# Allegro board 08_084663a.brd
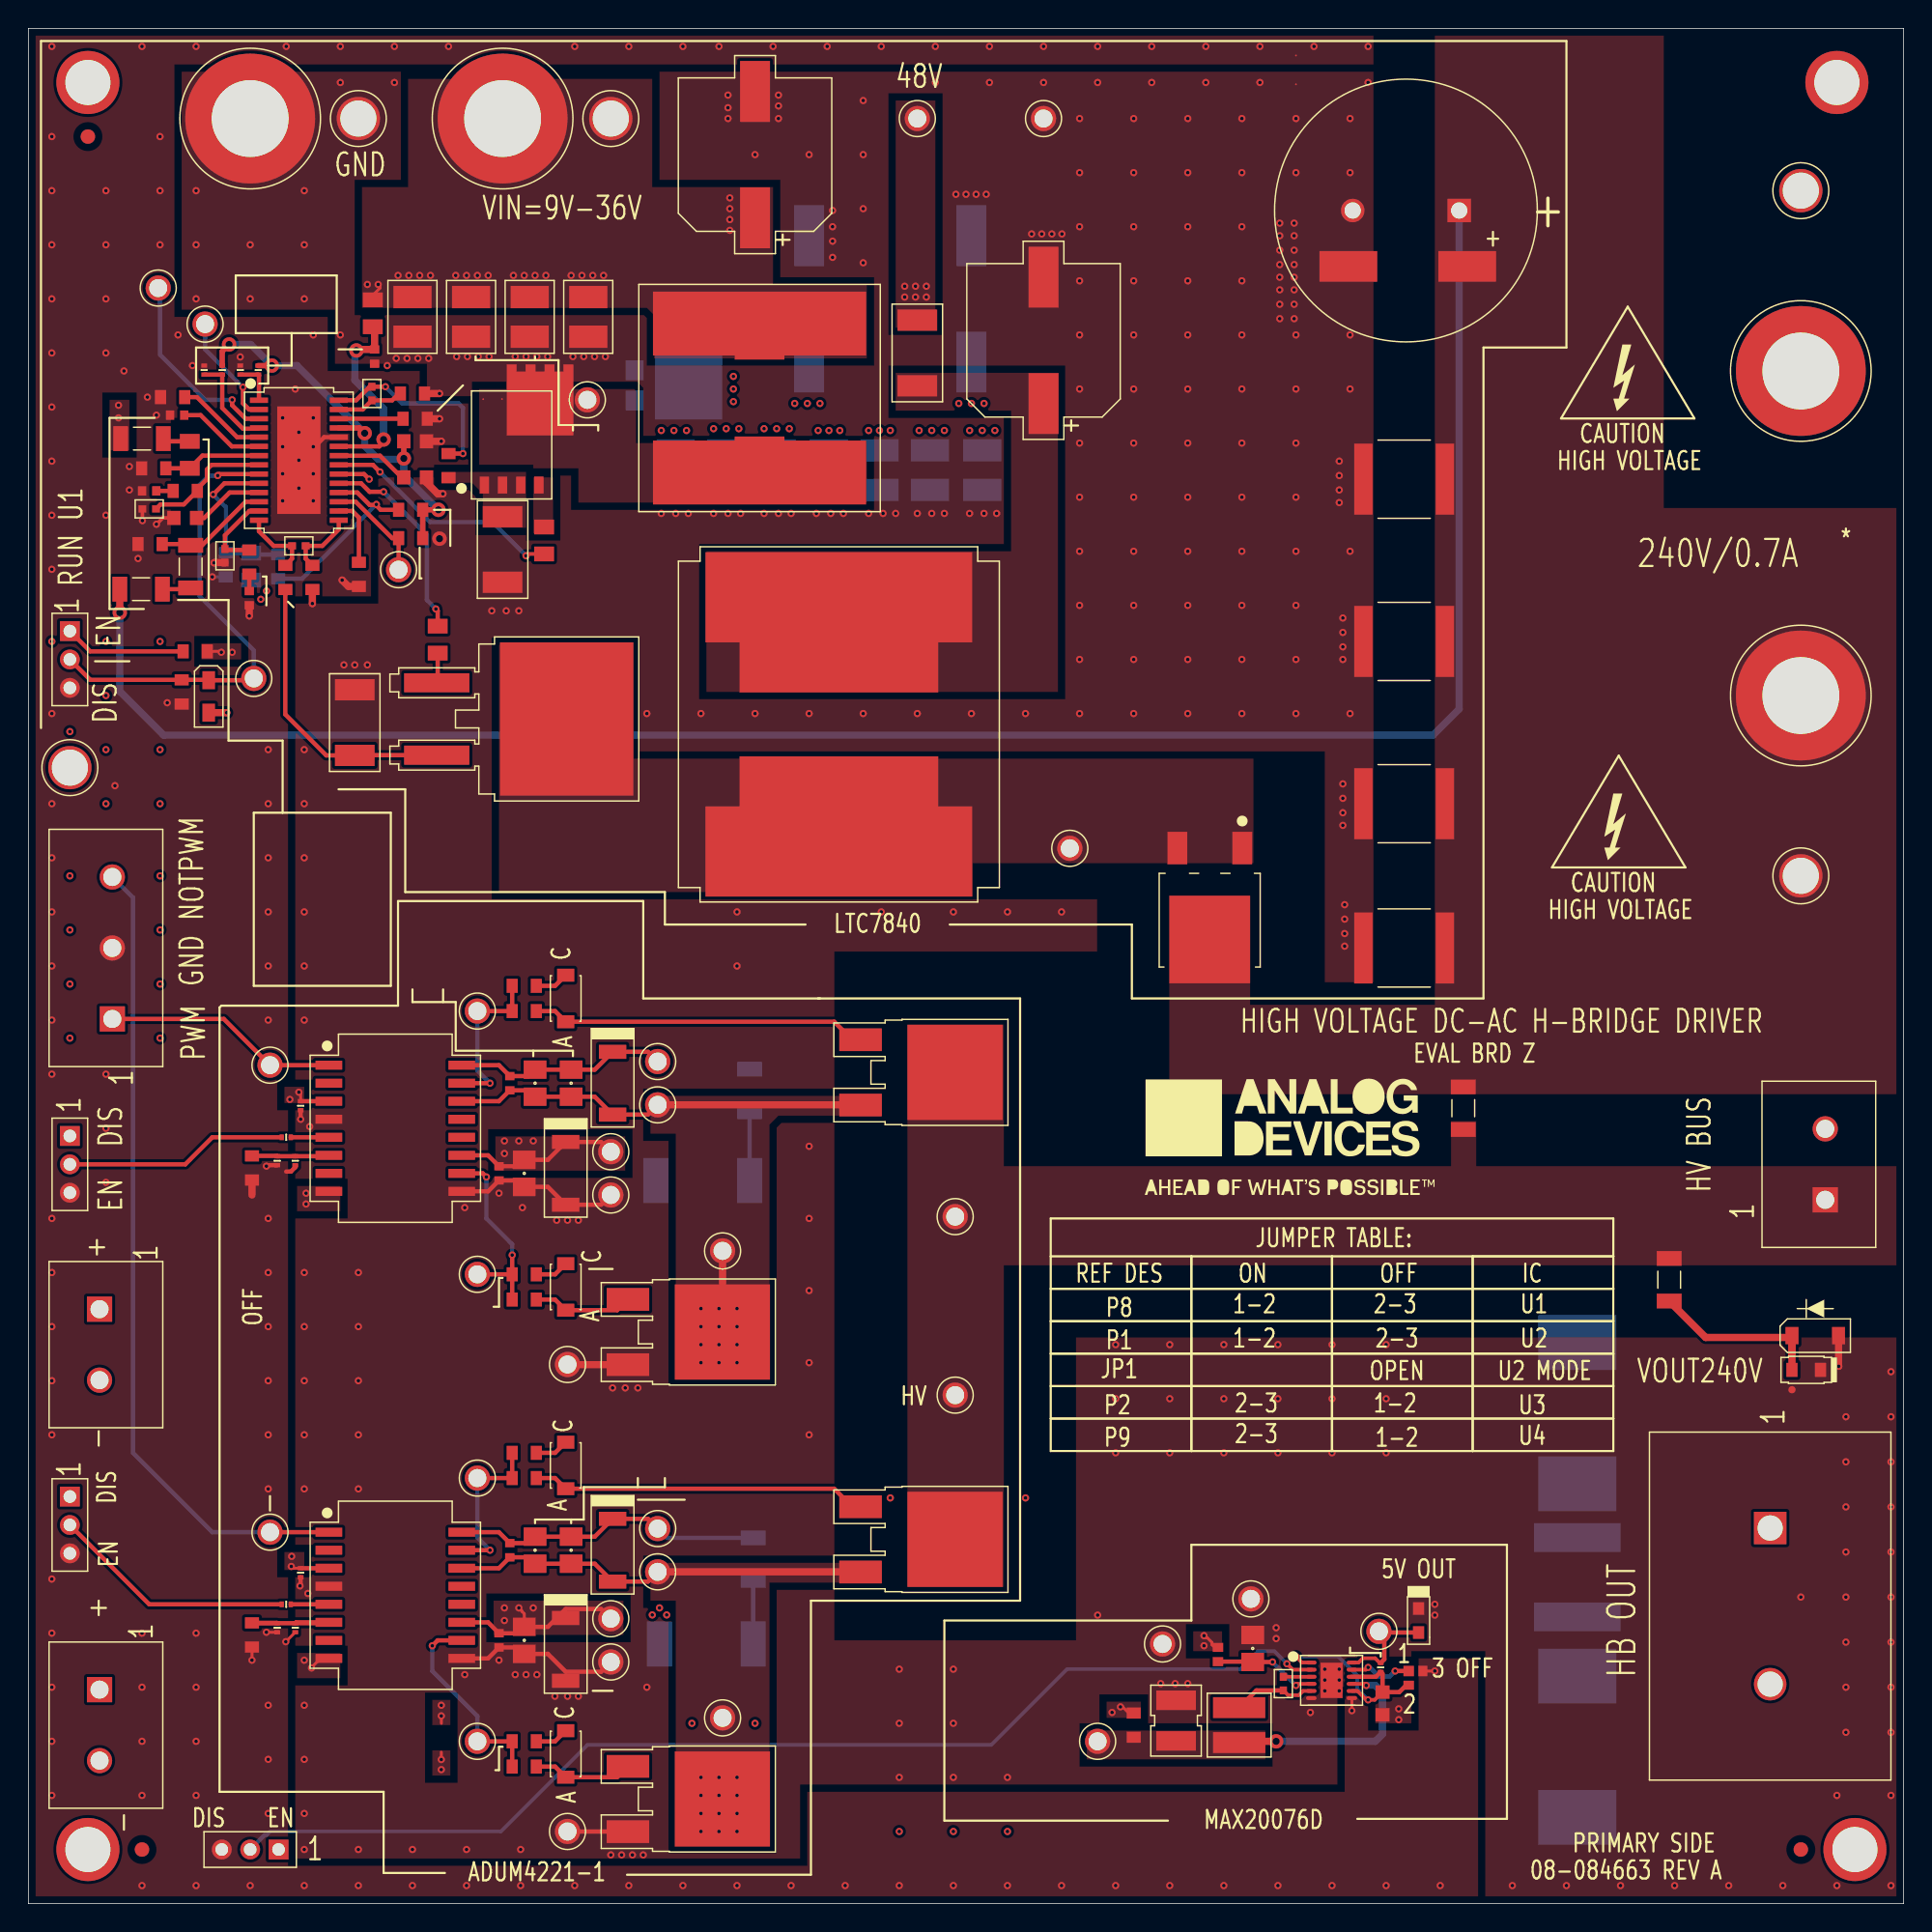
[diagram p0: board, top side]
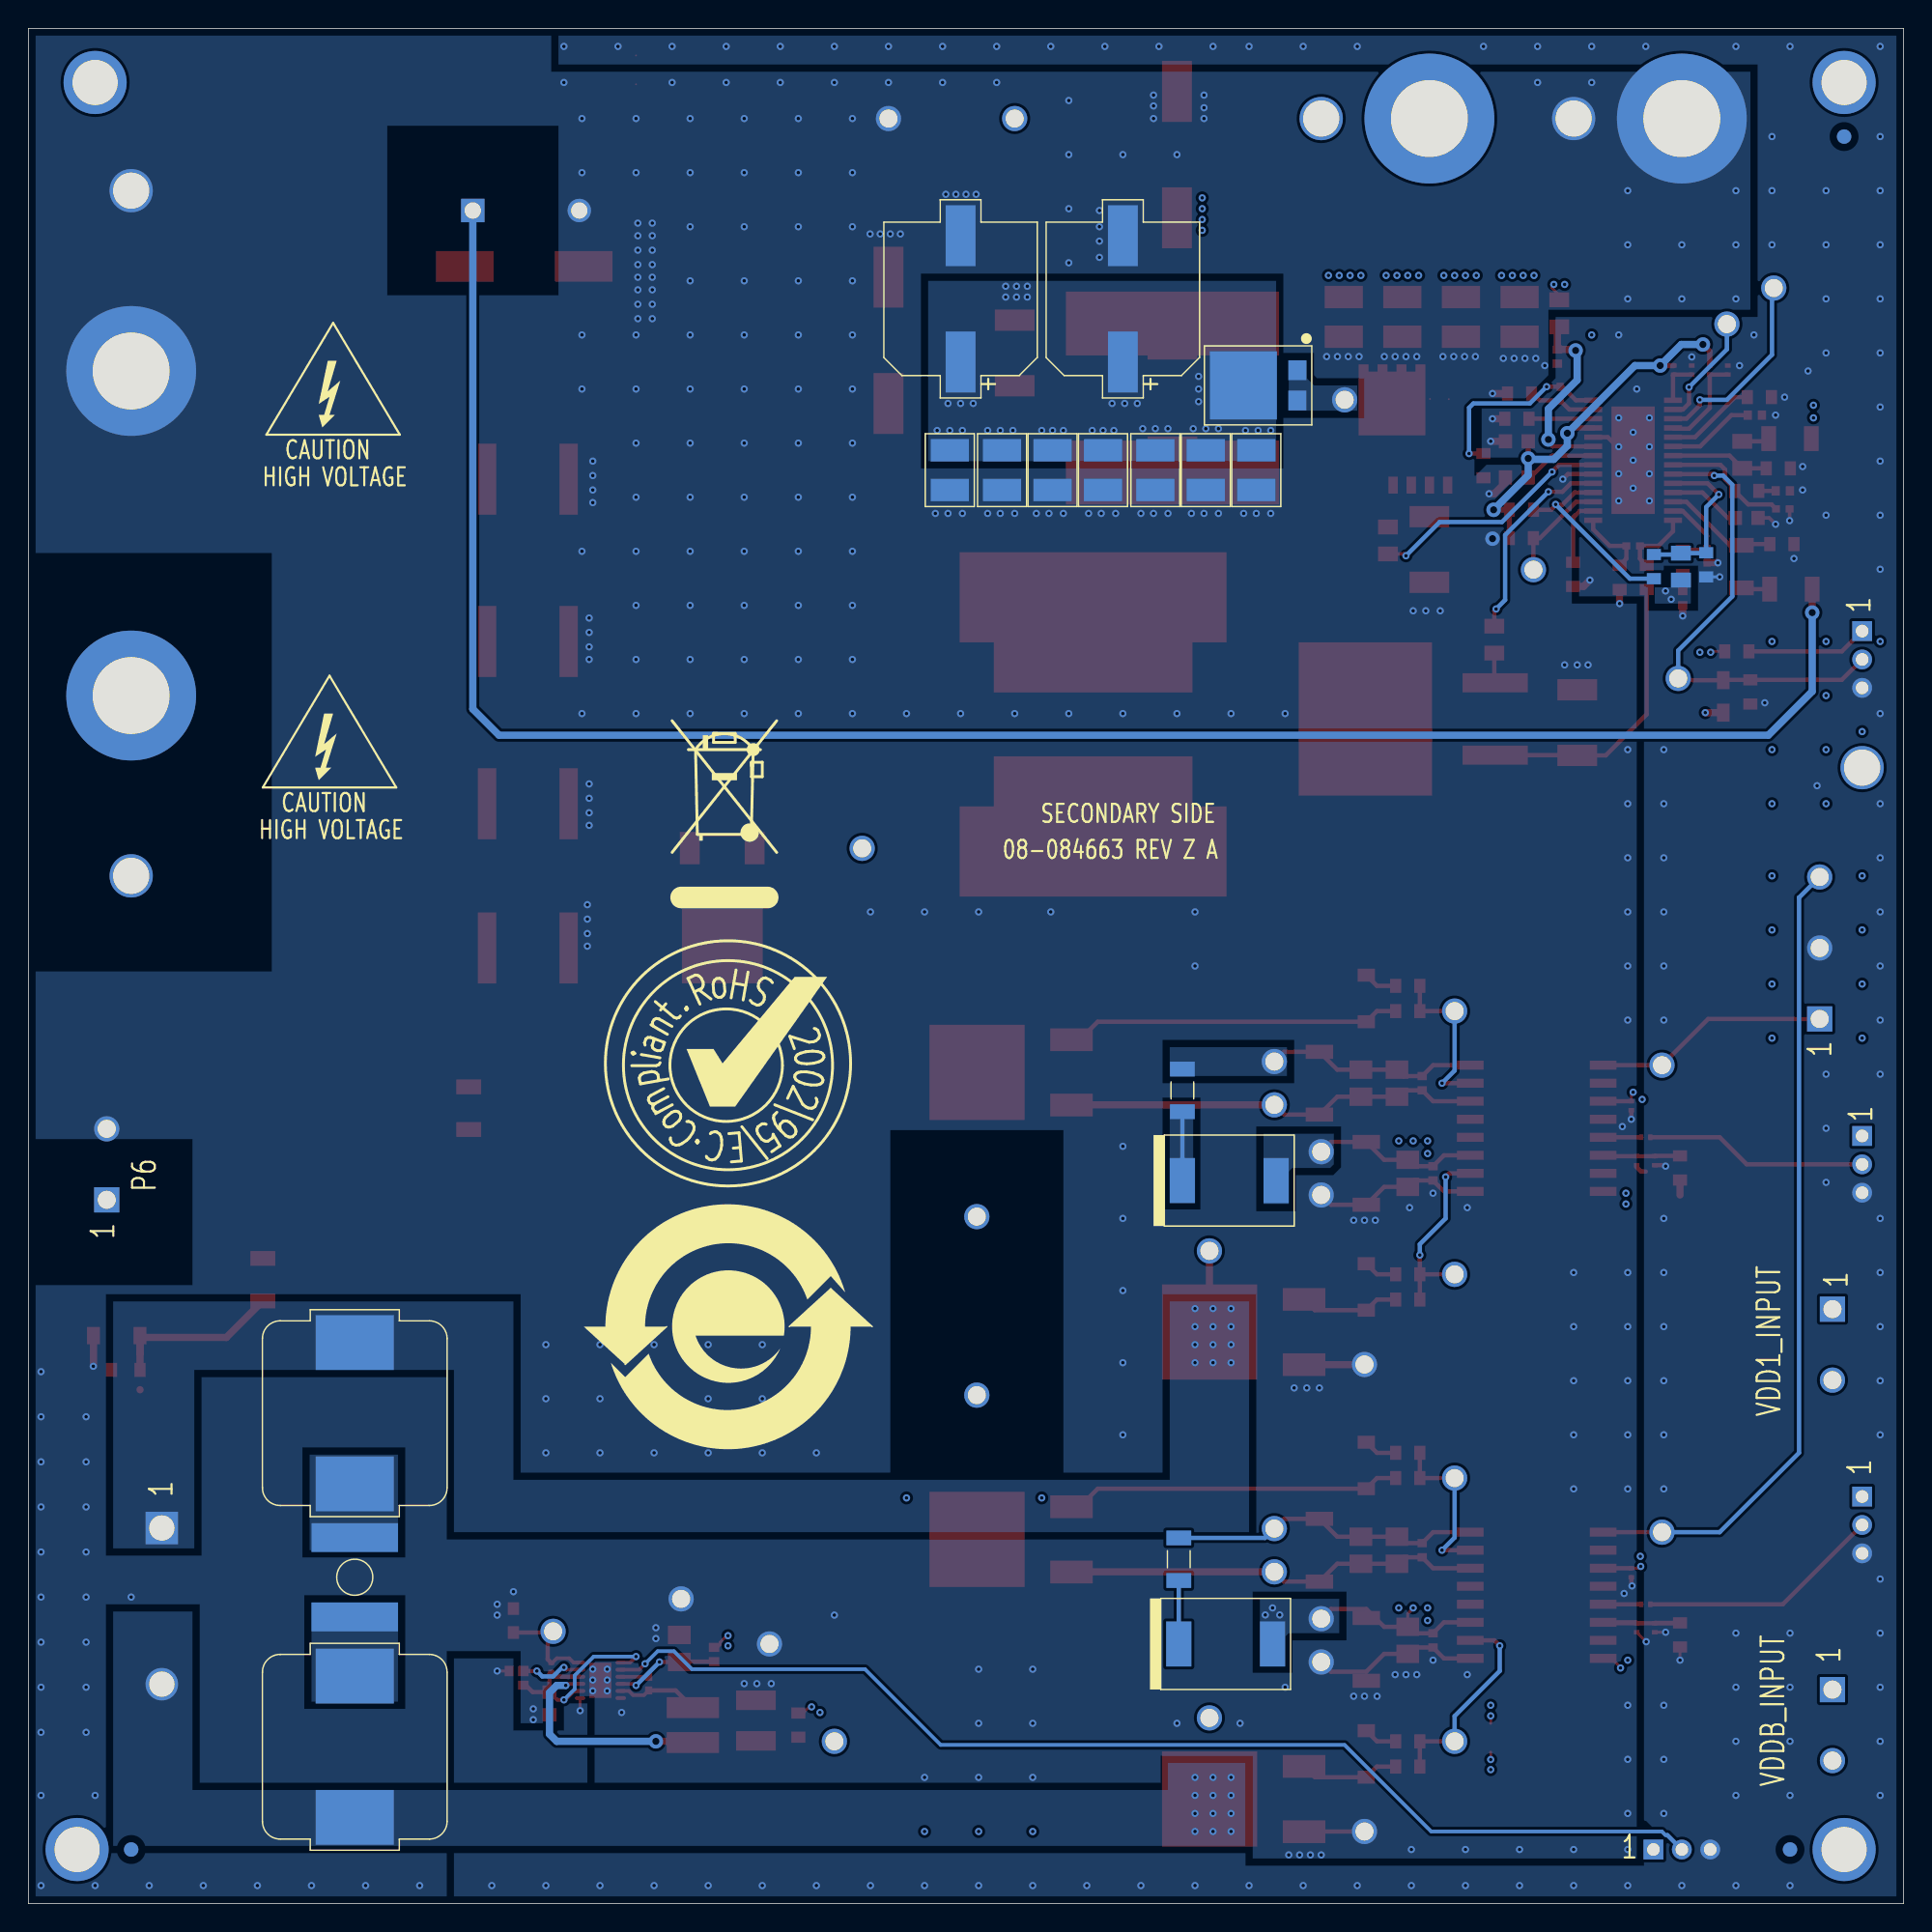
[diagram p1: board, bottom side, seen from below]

Outline 132.08 x 132.08 mm; copper layers: TOP, LAYER2_GND, LAYER3_PWR, BOTTOM. Coordinates in mm from the lower left corner of the outline.
Outline path: 0,132.08 0,0 132.08,0 132.08,132.08 0,132.08

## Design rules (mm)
constraint set DEFAULT: min track width 0.203
net group _N98: nets _N98 _N99
net group _N103: nets _N103 _N104
net group _N112: nets _N112 _N114
net group _N155: nets _N155 _N172
net group _N156: nets _N156 _N170
net group DISABLE: nets _N34 DISABLE
net group DISABLE_2: nets _N159 DISABLE_2
net group DRAINB_1: nets _N84 VDDA_2
net group LX: nets _N8 LX
net group RUN2: nets PGOOD1 RUN2
net group S1+: nets S1+ S1-
net group _N125: nets _N124
net group S2+: nets _N115 S2+ S2-

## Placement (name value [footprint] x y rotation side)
C1  0.1UF  [C0402]  24.38 108.97 270 top
C2  0.01uF  [C0402H22]  24.19 106.36 270 top
C3  1000pF  [C0603]  27.24 103 0 top
C4  4.7UF  [C0805H60]  86.23 17.97 90 top
C5  0.1UF  [C0402]  10.48 104.84 0 top
C6  10UF  [C0603H39]  27.24 100.46 0 top
C7  0.033uF  [C0402]  8.51 99.5 0 top
C8  100pF  [C0402H22]  8.51 98.23 0 top
C9  22UF  [C1210H110]  80.84 12.89 90 top
C10  2.2uF  [C0603]  11.05 97.6 0 top
C11  0.047uF  [C0402]  15.56 91.95 90 top
C12  0.01uF  [C0402H22]  19.05 95.63 0 top
C13  100pF  [C0402H22]  13.84 94.93 90 top
C14  1UF  [C0603H39]  95.38 14.1 270 top
C15  0.1uF  [C0402H22]  88.39 15.49 90 top
C16  0.1uF  [C0201]  19.18 56.2 270 top
C17  0.1uF  [C0201]  18.8 52.32 270 top
C18  4.7UF  [C0805H60]  35.69 57.79 270 top
C19  10UF  [C0805H60]  34.92 51.44 270 top
C20  10UF  [C0805H60]  38.23 57.79 270 top
C21  0.1uF  [C0402]  33.91 57.79 270 top
C22  0.1uF  [C0402]  33.15 51.44 270 top
C23  0.1uF  [C0201]  19.18 23.3 270 top
C24  0.1uF  [C0201]  18.8 19.43 270 top
C25  4.7UF  [C0805H60]  35.69 24.89 270 top
C26  10UF  [C0805H60]  34.92 18.54 270 top
C27  10UF  [C0805H60]  38.23 24.89 270 top
C28  0.1uF  [C0402]  33.91 24.89 270 top
C29  0.1uF  [C0402]  33.15 18.54 270 top
C30  0.022uF  [CSML215W230H35]  109.09 22.99 270 bottom
C31  2.2uF  [C2220-4]  96.9 100.33 180 top
C32  2.2uF  [C2220-4]  96.9 88.9 180 top
C33  2.2uF  [C2220-4]  96.9 77.47 180 top
C34  6.8UF  [CPLSMSQ406H433]  97.16 115.32 180 top
CIN1  33uF  [CPLSMSQ406H413]  51.18 123.19 90 top
CIN2  4.7UF  [C1210H95]  27.05 111.76 270 top
CIN3  4.7UF  [C1210H95]  31.18 111.76 270 top
CIN4  4.7UF  [C1210H95]  35.31 111.76 270 top
CIN5  4.7UF  [C1210H95]  39.43 111.76 270 top
CLKOUT  3137-3-00-21-00-00-08-0  [CNMILLMAX3137]  12.45 111.25 0 top
COUT1  4.7UF  [C1210H95]  45.59 100.97 270 bottom
COUT2  4.7UF  [C1210H95]  49.15 100.97 270 bottom
COUT3  4.7UF  [C1210H95]  52.7 100.97 270 bottom
COUT4  4.7UF  [C1210H95]  56.39 100.97 270 bottom
COUT5  33uF  [CPLSMSQ406H413]  54.99 113.03 90 bottom
COUT6  33uF  [CPLSMSQ406H413]  66.42 113.03 90 bottom
COUT10  2.2uF  [C2220-4]  96.9 67.31 180 top
COUT11  220UF  [CPLRAD295D709H1890LD31]  100.78 119.25 180 top
COUT13  4.7UF  [C1210H95]  59.94 100.97 270 bottom
COUT14  4.7UF  [C1210H95]  63.5 100.97 270 bottom
COUT15  4.7UF  [C1210H95]  67.18 100.97 270 bottom
COUT16  33uF  [CPLSMSQ406H413]  71.5 110.11 90 top
D1  V8P10-M3/86A  [TO-277A]  45.47 106.93 0 bottom
D2  PDZ6.8B,115  [SOD323]  12.7 85.03 270 top
D3  IDD04SG60CXTMA2  [TO252-3]  83.21 70.15 180 top
D4  VS-5ECU06-M3/9AT  [DO214AB-3]  47.5 50.93 180 bottom
D5  RB070MM-30TR  [SOD123FL]  37.85 63.75 270 top
D6  RB070MM-30TR  [SOD123FL]  37.85 43.43 270 top
D7  PDZVTFTR24B  [SOD128]  41.15 57.79 270 top
D8  PDZVTFTR24B  [SOD128]  37.85 51.44 270 top
D9  VS-5ECU06-M3/9AT  [DO214AB-3]  47.75 18.29 180 bottom
D10  RB070MM-30TR  [SOD123FL]  37.85 30.86 270 top
D11  RB070MM-30TR  [SOD123FL]  37.85 10.54 270 top
D12  PDZVTFTR24B  [SOD128]  41.15 24.89 270 top
D13  PDZVTFTR24B  [SOD128]  37.85 17.91 270 top
D14  MMSZ4678-TP  [SOD123-2]  125.86 40.01 0 top
DRAINA_1  3137-3-00-21-00-00-08-0  [CNMILLMAX3137]  65.28 48.39 0 top
DRAINB_1  3137-3-00-21-00-00-08-0  [CNMILLMAX3137]  48.89 45.97 270 top
DRAINB_2  3137-3-00-21-00-00-08-0  [CNMILLMAX3137]  48.89 13.08 270 top
DS1  LTST-C191KGKT  [LED0603_A]  97.92 19.94 270 top
DS2  LS M67K-H2L1-1-Z  [LEDSML79W55H55]  125.22 37.59 180 top
EXTCLK  3137-3-00-21-00-00-08-0  [CNMILLMAX3137]  9.14 113.79 0 top
GND  2501-2-00-80-00-00-07-0  [CNMILLMAX2501]  124.84 120.65 0 top
GND_3  2501-2-00-80-00-00-07-0  [CNMILLMAX2501]  2.92 80.01 0 top
GND_5  3137-3-00-21-00-00-08-0  [CNMILLMAX3137]  79.88 18.29 0 top
GNDA  3137-3-00-21-00-00-08-0  [CNMILLMAX3137]  44.32 56.26 0 top
GNDA_2  3137-3-00-21-00-00-08-0  [CNMILLMAX3137]  44.32 23.37 0 top
GNDB  3137-3-00-21-00-00-08-0  [CNMILLMAX3137]  41.02 49.91 270 top
GNDB_2  3137-3-00-21-00-00-08-0  [CNMILLMAX3137]  37.97 5.08 0 top
GNDB_3  3137-3-00-21-00-00-08-0  [CNMILLMAX3137]  37.97 37.97 0 top
GNDB_4  3137-3-00-21-00-00-08-0  [CNMILLMAX3137]  41.02 17.02 270 top
HB  YK7010223000G  [CNAMPYK70102]  122.68 26.46 270 top
J1  575-4  [CNBANANAD312LD203]  124.84 85.09 180 top
J2  575-4  [CNBANANAD312LD203]  124.84 107.95 0 top
J3  575-4  [CNBANANAD312LD203]  33.4 125.73 0 top
J4  575-4  [CNBANANAD312LD203]  15.62 125.73 0 top
JP1  3PIN_JUMPER  [3PINJUMPER_0402_NPM]  97.22 16.38 180 top
L1  10UH  [LSML610W650H512]  51.5 106.05 270 top
L2  100UH  [LSML885W870H512]  57.09 83.06 270 top
L3  4.7uH  [LSMSQ157H83]  85.28 12.57 270 top
L4  47UH  [LSMSQ492H315_2P]  109.09 34.54 270 bottom
L5  180UH  [LSMD512H287]  57.09 83.06 270 top
L6  47UH  [LSMSQ492H315_2P]  109.09 11.05 90 bottom
L7  10UH  [LSML433W394H157]  51.5 106.05 270 top
NOREF  -  []  257.33 -70.63 0 top
NOREF#2  -  []  88.27 53.98 0 top
NOREF#3  -  []  -139.42 130.18 0 top
NOREF#4  -  []  0 0 0 top
NOREF#5  -  []  506.73 -48.26 0 top
NOREF#6  -  [unnamed#2]  127.38 128.27 0 top
NOREF#7  -  []  111.76 75.78 0 top
NOREF#8  -  [unnamed#2]  128.65 3.81 0 top
NOREF#9  -  []  -139.37 107.31 0 top
NOREF#10  -  []  -220.6 -323.85 0 top
NOREF#11  -  []  329.72 -93.18 90 top
NOREF#12  -  []  198.28 142.62 0 top
NOREF#13  -  []  219.73 -69.05 0 top
NOREF#14  -  []  449.58 -43.18 0 top
NOREF#15  -  []  132.08 132.08 180 top
NOREF#16  -  []  -220.6 -323.85 0 top
NOREF#17  -  []  112.4 107.4 0 top
NOREF#18  -  []  132.08 -0.05 90 top
NOREF#19  -  []  166.01 -20.38 270 top
NOREF#20  -  []  380.43 -37.46 0 top
NOREF#21  -  []  74.48 144.57 0 top
NOREF#22  -  [unnamed#2]  4.19 124.46 0 top
NOREF#23  -  [unnamed#2]  4.19 128.27 0 top
NOREF#24  -  []  380.4 -64.11 0 top
NOREF#25  -  []  184.98 109.41 0 top
NOREF#26  -  []  476.02 -43.17 0 top
NOREF#27  -  []  329.72 -69.05 90 top
NOREF#28  -  [unnamed#2]  124.84 3.81 0 top
NOREF#29  -  []  -143.13 153.04 0 top
NOREF#30  -  []  104.18 0 90 top
NOREF#31  -  []  -220.6 -323.85 0 top
NOREF#32  -  []  0 129.7 0 top
NOREF#33  -  []  133.1 186.06 0 top
NOREF#34  -  []  380.28 -43.16 0 top
NOREF#35  -  [unnamed#2]  4.19 3.81 0 top
NOREF#36  -  []  474.53 -53.33 0 top
NOREF#37  -  []  200.82 -75.08 0 top
NOREF#38  -  []  0 132.08 270 top
NOREF#39  -  []  220.9 -79.21 0 top
NOREF#40  -  [unnamed#2]  8 3.81 0 top
NOREF#41  -  [unnamed#2]  8 3.81 180 bottom
NOREF#42  -  []  110.87 106.26 180 bottom
NOREF#43  -  [unnamed#2]  124.84 3.81 180 bottom
NOREF#44  -  []  73.79 87 180 bottom
NOREF#45  -  []  82.8 40.64 180 bottom
NOREF#46  -  [unnamed#2]  4.19 124.46 180 bottom
NOREF#47  -  []  111.12 81.41 180 bottom
NOREF#48  -  []  82.8 59.06 180 bottom
NOT_PWM  3137-3-00-21-00-00-08-0  [CNMILLMAX3137]  17.02 26.16 0 top
P1  62000311121  [CNTHMHDR1X3L236W79H244]  17.62 3.81 180 top
P2  62000311121  [CNTHMHDR1X3L236W79H244]  2.92 54.07 270 top
P5  OSTTC030162  [CNOSTTC030162]  5.91 62.31 90 top
P6  OSTTC020162  [CNOSTTC0201X2]  126.56 49.57 90 top
P8  62000311121  [CNTHMHDR1X3L236W79H244]  2.92 89.63 270 top
P9  62000311121  [CNTHMHDR1X3L236W79H244]  2.92 28.67 270 top
PGOOD  3137-3-00-21-00-00-08-0  [CNMILLMAX3137]  26.07 93.95 0 top
PGOOD_2  3137-3-00-21-00-00-08-0  [CNMILLMAX3137]  95.12 19.18 0 top
PWM  3137-3-00-21-00-00-08-0  [CNMILLMAX3137]  17.02 59.06 0 top
Q1  BSC047N08NS3GATMA1  [SON8]  34.04 102.74 0 top
Q2  TK12P50W,RQ  [TO252]  62.68 58.55 270 top
Q3  STB45N40DM2AG  [TO263-3]  33.34 83.44 270 top
Q4  TK12P50W,RQ  [TO252]  46.29 40.26 270 top
Q5  TK12P50W,RQ  [TO252]  62.68 25.65 270 top
Q6  TK12P50W,RQ  [TO252]  46.29 7.37 270 top
R1  2.2  [R0805]  24.26 112.01 270 top
R2  3K  [R0201]  95.25 16.64 90 top
R3  0  [R0603]  77.85 12.57 90 top
R4  1K  [R0201]  18.16 53.98 0 top
R5  10K  [R0201]  17.53 52.32 270 top
R6  10  [R0603]  29.59 101.28 270 top
R7  200K  [R0603]  15.75 51.82 270 top
R8  1  [R1206]  50.8 57.28 270 bottom
R9  1  [R0603]  34.92 64.64 0 top
R10  4.02  [R0603]  34.92 62.87 0 top
R11  84.5K  [R0603]  11.75 88.2 180 top
R12  73.2K  [R0603]  10.16 106.11 0 top
R13  12.1K  [R0603]  10.79 85.34 90 top
R14  12.1K  [R0603]  8.83 101.09 180 top
R15  1  [R0603]  34.92 44.32 0 top
R16  475K  [R0805]  11.37 102.04 270 top
R17  5.62K  [R0603]  11.05 99.5 0 top
R18  4.02  [R0603]  34.92 42.55 0 top
R19  487K  [R0805]  15.68 94.17 270 bottom
R20  11.8K  [R0603]  8.57 95.76 180 top
R21  10K  [R0201]  17.53 19.43 270 top
R22  2.37M  [R1206]  11.43 94.17 90 top
R23  10  [R0603]  18.1 93.41 270 top
R24  200K  [R0603]  15.75 18.92 270 top
R25  12.1K  [R0603]  13.91 94.3 270 bottom
R26  46.4K  [R0603]  15.56 94.49 90 top
R27  1  [R1206]  51.05 24.26 270 bottom
R28  1  [R0603]  34.92 31.75 0 top
R29  100K  [R0603]  26.92 98.17 0 top
R30  100K  [R0603]  26.92 96.18 180 top
R31  4.02  [R0603]  34.92 29.97 0 top
R32  1  [R0603]  34.92 11.43 0 top
R33  4.02  [R0603]  34.92 9.65 0 top
R34  0  [R0603]  20 93.41 270 top
R35  0  [R0603]  23.28 93.62 270 top
R36  0  [R0805]  28.83 89.03 270 top
R37  0  [R0603]  27.24 104.58 0 top
R38  0  [R0603]  27.05 106.36 0 top
R39  0  [R0805]  36.32 96.01 90 top
R40  0  [R0603]  17.59 94.17 270 bottom
R41  3K  [R0201]  16.19 108.01 270 top
R42  3K  [R0201]  13.65 108.01 270 top
R43  3K  [R0201]  14.92 108.01 270 top
R44  3K  [R0201]  12.38 108.01 270 top
R45  1K  [R0201]  18.16 21.08 0 top
R46  0  [R1206]  101.07 56.02 270 top
R47  0  [R0402]  83.79 17.55 270 top
R48  10  [R1206]  7.94 92.58 0 top
R49  10  [R1206]  8 103.19 0 top
R50  120K  [R1206]  115.57 43.94 90 top
RS1  0.002  [R2010H35]  33.4 95.38 270 top
RS3  0.008  [R2010H35]  22.99 83.19 90 top
RS4  0.001  [R2010H35]  62.61 109.22 270 top
RUN  3137-3-00-21-00-00-08-0  [CNMILLMAX3137]  15.88 86.3 0 top
SNS1  SNS  [NCSNS50MIL]  89.28 128.14 90 top
SNS2  SNS  [NCSNS50MIL]  29.08 10.67 90 top
SW1  3137-3-00-21-00-00-08-0  [CNMILLMAX3137]  39.37 105.92 180 top
SW2  3137-3-00-21-00-00-08-0  [CNMILLMAX3137]  73.35 74.33 0 top
TP2  3137-3-00-21-00-00-08-0  [CNMILLMAX3137]  86.11 21.46 0 top
TP3  3137-3-00-21-00-00-08-0  [CNMILLMAX3137]  65.28 35.81 0 top
U1  LTC7840HFE#PBF  [TSSOP28_PAD7_56X3_05]  19.05 101.66 270 top
U2  MAX20076DATCA/V+  [DFN12_3X3_PAD2_5X1_55]  91.79 15.73 270 top
U3  ADUM4221-1CRIZ  [SO16H104]  25.84 54.61 270 top
U4  ADUM4221-1CRIZ  [SO16H104]  25.84 21.72 270 top
UNK5V_RAIL  3137-3-00-21-00-00-08-0  [CNMILLMAX3137]  75.31 11.43 0 top
VDD1_INPUT  OSTTC020162  [CNOSTTC0201X2]  5.01 41.87 270 top
VDDA  3137-3-00-21-00-00-08-0  [CNMILLMAX3137]  44.32 59.31 0 top
VDDA_2  3137-3-00-21-00-00-08-0  [CNMILLMAX3137]  44.32 26.42 0 top
VDDB  3137-3-00-21-00-00-08-0  [CNMILLMAX3137]  41.02 52.96 0 top
VDDB_2  3137-3-00-21-00-00-08-0  [CNMILLMAX3137]  41.02 20.07 0 top
VDDB_INPUT  OSTTC020162  [CNOSTTC0201X2]  5.01 15.07 270 top
VIN  2501-2-00-80-00-00-07-0  [CNMILLMAX2501]  41.02 125.73 0 top
VIN_GND  2501-2-00-80-00-00-07-0  [CNMILLMAX2501]  23.24 125.73 0 top
VOA_1  3137-3-00-21-00-00-08-0  [CNMILLMAX3137]  31.62 62.87 0 top
VOA_2  3137-3-00-21-00-00-08-0  [CNMILLMAX3137]  31.62 29.97 0 top
VOB_1  3137-3-00-21-00-00-08-0  [CNMILLMAX3137]  31.62 44.32 270 top
VOB_2  3137-3-00-21-00-00-08-0  [CNMILLMAX3137]  31.62 11.43 270 top
VOUT1  3137-3-00-21-00-00-08-0  [CNMILLMAX3137]  62.61 125.73 0 top
VOUT_240V  2501-2-00-80-00-00-07-0  [CNMILLMAX2501]  124.84 72.39 180 top
VOUT_GND  3137-3-00-21-00-00-08-0  [CNMILLMAX3137]  71.5 125.73 0 top

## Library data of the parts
C1 C5 C7 C11 C21 C22 C28 C29 = CAP: User Part Number: UPN; Tolerance: 10; alternate symbols: (C0402); tolerance: 10
C2 C8 C12 C13 = CAP: Tolerance: 5; User Part Number: UPN; alternate symbols: (C0402H22); tolerance: 5
C3 = CAP: User Part Number: UPN; Tolerance: 5; alternate symbols: (C0603); tolerance: 5
C4 C18-C20 C25-C27 = CAP: Tolerance: 10; User Part Number: UPN; alternate symbols: (C0805H60); tolerance: 10
C6 = CAP: User Part Number: UPN; Tolerance: 20; alternate symbols: (C0603H39); tolerance: 20
C9 = CAP: Tolerance: 10; User Part Number: UPN; alternate symbols: (C1210H110); tolerance: 10
C10 = CAP: User Part Number: UPN; Tolerance: 10; alternate symbols: (C0603); tolerance: 10
C14 = CAP: User Part Number: UPN; Tolerance: 10; alternate symbols: (C0603H39); tolerance: 10
C15 = CAP: Tolerance: 10; User Part Number: UPN; alternate symbols: (C0402H22); tolerance: 10
C16 C17 C23 C24 = CAP: Tolerance: 10; User Part Number: UPN; alternate symbols: (C0201); tolerance: 10
C30 = CAP: Tolerance: 1; User Part Number: UPN; alternate symbols: (CSML215W230H35); tolerance: 1
C31-C33 COUT10 = CAP: Tolerance: 10; User Part Number: UPN; alternate symbols: (C2220-4); tolerance: 10
C34 = CAPP: User Part Number: UPN; Tolerance: 20; alternate symbols: (CPLSMSQ406H433); tolerance: 20
CIN1 COUT5 COUT6 COUT16 = CAPP: User Part Number: UPN; Tolerance: 20; alternate symbols: (CPLSMSQ406H413); tolerance: 20
CIN2-CIN5 COUT1-COUT4 COUT13-COUT15 = CAP: Tolerance: 10; User Part Number: UPN; alternate symbols: (C1210H95); tolerance: 10
CLKOUT DRAINA_1 DRAINB_1 DRAINB_2 EXTCLK GND_5 GNDA GNDA_2 GNDB GNDB_2-GNDB_4 NOT_PWM PGOOD PGOOD_2 PWM RUN SW1 SW2 TP2 TP3 UNK5V_RAIL VDDA VDDA_2 VDDB VDDB_2 VOA_1 VOA_2 VOB_1 VOB_2 VOUT1 VOUT_GND = CNTP1P: Tolerance: N/A; User Part Number: UPN; alternate symbols: (CNMILLMAX3137); tolerance: N/A
COUT11 = CAPP: User Part Number: UPN; Tolerance: 20; alternate symbols: (CPLRAD295D709H1890LD31); tolerance: 20
D1 = DIOSCHOTTKY_3P: User Part Number: UPN; Tolerance: N/A; alternate symbols: (TO-277A); tolerance: N/A
D2 = DIOZNR: Tolerance: 2; User Part Number: UPN; alternate symbols: (SOD323); tolerance: 2
D3 = DIOSCHOTTKY3P_V18: Tolerance: N/A; User Part Number: UPN; alternate symbols: (TO252-3); tolerance: N/A
D4 D9 = DIO: User Part Number: UPN; Tolerance: N/A; alternate symbols: (DO214AB-3); tolerance: N/A
D5 D6 D10 D11 = DIOSCHOTTKY: User Part Number: UPN; Tolerance: N/A; alternate symbols: (SOD123FL); tolerance: N/A
D7 D8 D12 D13 = DIOZNR: User Part Number: UPN; Tolerance: 7.5; alternate symbols: (SOD128); tolerance: 7.5
D14 = DIOZNR: User Part Number: UPN; Tolerance: 5; alternate symbols: (SOD123-2); tolerance: 5
DS1 = DIOLED: User Part Number: UPN; Tolerance: N/A; alternate symbols: (LED0603_A); tolerance: N/A
DS2 = DIOLED: User Part Number: UPN; Tolerance: N/A; alternate symbols: (LEDSML79W55H55); tolerance: N/A
GND GND_3 VIN VIN_GND VOUT_240V = CNTP1P: User Part Number: UPN; Tolerance: N/A; alternate symbols: (CNMILLMAX2501); tolerance: N/A
HB = CN2P: User Part Number: UPN; Tolerance: N/A; alternate symbols: (CNAMPYK70102); tolerance: N/A
J1-J4 = CNTP1P: Tolerance: N/A; User Part Number: UPN; alternate symbols: (CNBANANAD312LD203); tolerance: N/A
JP1 = NC3P_JMPR: User Part Number: UPN; Tolerance: N/A; alternate symbols: (3PINJUMPER_0402_NPM); tolerance: N/A
L1 = IND: User Part Number: UPN; Tolerance: 20; alternate symbols: (LSML610W650H512); tolerance: 20
L2 = IND: User Part Number: UPN; Tolerance: 20; alternate symbols: (LSML885W870H512); tolerance: 20
L3 = IND: User Part Number: UPN; Tolerance: 20; alternate symbols: (LSMSQ157H83); tolerance: 20
L4 L6 = IND_V10: Tolerance: 20; User Part Number: UPN; alternate symbols: (LSMSQ492H315_2P); tolerance: 20
L5 = IND_V4: User Part Number: UPN; Tolerance: 10; alternate symbols: (LSMD512H287); tolerance: 10
L7 = IND: User Part Number: UPN; Tolerance: 20; alternate symbols: (LSML433W394H157); tolerance: 20
P1 P2 P8 P9 = CN3P: User Part Number: UPN; Tolerance: N/A; alternate symbols: (CNTHMHDR1X3L236W79H244); tolerance: N/A
P5 = CN3P: User Part Number: UPN; Tolerance: N/A; alternate symbols: (CNOSTTC030162); tolerance: N/A
P6 VDD1_INPUT VDDB_INPUT = CN2P: Tolerance: N/A; User Part Number: UPN; alternate symbols: (CNOSTTC0201X2); tolerance: N/A
Q1 = TRANNMOSFET_V15: Tolerance: N/A; User Part Number: UPN; alternate symbols: (SON8); tolerance: N/A
Q2 Q4-Q6 = TRANNMOSFET_V10: User Part Number: UPN; Tolerance: N/A; alternate symbols: (TO252); tolerance: N/A
Q3 = TRANNMOSFET_V35: User Part Number: UPN; Tolerance: N/A; alternate symbols: (TO263-3); tolerance: N/A
R1 R16 R19 = RES: User Part Number: UPN; Tolerance: 1; alternate symbols: (R0805); tolerance: 1
R2 R4 R5 R21 R41-R45 = RES: Tolerance: 1; User Part Number: UPN; alternate symbols: (R0201); tolerance: 1
R3 R34 R35 R37 R38 R40 = RES: User Part Number: UPN; Tolerance: JUMPER; alternate symbols: (R0603); tolerance: JUMPER
R6 R10-R14 R17 R18 R20 R23 R25 R26 R29-R31 R33 = RES: User Part Number: UPN; Tolerance: 1; alternate symbols: (R0603); tolerance: 1
R7 R24 = RES: User Part Number: UPN; Tolerance: 5; alternate symbols: (R0603); tolerance: 5
R8 R27 = RES: User Part Number: UPN; alternate symbols: (R1206)
R9 R15 R28 R32 = RES: User Part Number: UPN; alternate symbols: (R0603)
R22 R48-R50 = RES: User Part Number: UPN; Tolerance: 1; alternate symbols: (R1206); tolerance: 1
R36 R39 = RES: User Part Number: UPN; Tolerance: JUMPER; alternate symbols: (R0805); tolerance: JUMPER
R46 = RES: User Part Number: UPN; Tolerance: JUMPER; alternate symbols: (R1206); tolerance: JUMPER
R47 = RES: User Part Number: UPN; Tolerance: JUMPER; alternate symbols: (R0402); tolerance: JUMPER
RS1 RS3 RS4 = RES: Tolerance: 1; User Part Number: UPN; alternate symbols: (R2010H35); tolerance: 1
SNS1 SNS2 = NCSENSE: User Part Number: UPN; Tolerance: N/A; alternate symbols: (NCSNS50MIL); tolerance: N/A
U1 = ADLTC7840: User Part Number: UPN; Tolerance: N/A; alternate symbols: (TSSOP28_PAD7_56X3_05); tolerance: N/A
U2 = ADMAX2007X: User Part Number: UPN; Tolerance: N/A; alternate symbols: (DFN12_3X3_PAD2_5X1_55); tolerance: N/A
U3 U4 = ADUM4221_1: User Part Number: UPN; Tolerance: N/A; alternate symbols: (SO16H104); tolerance: N/A

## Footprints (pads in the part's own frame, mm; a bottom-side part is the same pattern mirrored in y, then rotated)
3PINJUMPER_0402_NPM
  rect 0.737x0.635 smd: 1(0,1.001)
  rect 0.737x0.737 smd: 2(0,0)
  rect 0.635x0.737 smd: 3(-1.001,0)
C0201
  rect 0.305x0.406 smd: 1(-0.318,0) 2(0.318,0)
C0402
  rect 0.584x0.66 smd: 1(-0.5,0) 2(0.5,0)
C0402H22
  rect 0.559x0.508 smd: 1(-0.479,0) 2(0.479,0)
C0603
  rect 0.94x0.991 smd: 1(-0.8,0) 2(0.8,0)
C0603H39
  rect 0.94x0.991 smd: 1(-0.8,0) 2(0.8,0)
C0805H60
  rect 1.295x1.6 smd: 1(-0.953,0) 2(0.953,0)
C1210H95
  rect 1.575x2.692 smd: 1(-1.397,0) 2(1.397,0)
C1210H110
  rect 1.372x2.794 smd: 1(-1.431,0) 2(1.431,0)
C2220-4
  rect 1.295x5.004 smd: 1(-2.873,0) 2(2.873,0)
CNAMPYK70102
  rect 2.286x2.286 hole 1.778: 1(0,0)
  round 2.286 hole 1.778: 2(11,0)
CNBANANAD312LD203
  round 9.144 hole 5.41: 1(0,0)
CNMILLMAX2501
  round 3.048 hole 2.54: 1(0,0)
CNMILLMAX3137
  round 1.778 hole 1.27: 1(0,0)
CNOSTTC0201X2
  rect 1.778x1.778 hole 1.27: 1(0,0)
  round 1.778 hole 1.27: 2(5,0)
CNOSTTC030162
  rect 1.778x1.778 hole 1.27: 1(0,0)
  round 1.778 hole 1.27: 2(5,0) 3(10,0)
CNTHMHDR1X3L236W79H244
  rect 1.397x1.397 hole 0.889: 1(0,0)
  round 1.397 hole 0.889: 2(2,0) 3(4,0)
CPLRAD295D709H1890LD31
  round 1.651 hole 1.143: N(7.5,0)
  rect 1.651x1.651 hole 1.143: P(0,0)
CPLSMSQ406H413
  rect 4.293x2.108 smd: N(4.45,0) P(-4.45,0)
CPLSMSQ406H433
  rect 4.064x2.159 smd: N(4.187,0) P(-4.187,0)
CSML215W230H35
  rect 2.032x6.096 smd: 1(-2.794,0) 2(2.794,0)
DFN12_3X3_PAD2_5X1_55
  oval 0.279x0.737 smd: 1(-1.25,-1.43) 2(-0.75,-1.43) 3(-0.25,-1.43) 4(0.25,-1.43) 5(0.75,-1.43) 6(1.25,-1.43) 7(1.25,1.43) 8(0.75,1.43) 9(0.25,1.43) 10(-0.25,1.43) 11(-0.75,1.43) 12(-1.25,1.43)
  rect 2.489x1.549 smd: PAD(0,0)
DO214AB-3
  rect 1.778x3.175 smd: A(3.302,0) C(-3.302,0)
LED0603_A
  rect 0.889x0.787 smd: A(0.845,0) C(-0.845,0)
LEDSML79W55H55
  rect 0.787x0.991 smd: A(1.006,0) C(-1.006,0)
LSMD512H287
  rect 4.75x13.995 smd: 1(-4.625,0) 2(4.625,0)
LSML433W394H157
  rect 4.089x3.505 smd: 1(-4.755,0) 2(4.755,0)
LSML610W650H512
  rect 4.496x15.011 smd: 1(-5.248,0) 2(5.248,0)
LSML885W870H512
  rect 6.35x18.796 smd: 1(-8.954,0) 2(8.954,0)
LSMSQ157H83
  rect 1.473x3.683 smd: 1(-1.232,0) 2(1.232,0)
LSMSQ492H315_2P
  rect 3.861x5.512 smd: 1(-4.975,0) 2(4.975,0)
NCSNS50MIL
  round 0.127 smd: 1(0,0) 2(2.032,0)
R0201
  rect 0.305x0.406 smd: 1(-0.318,0) 2(0.318,0)
R0402
  rect 0.635x0.737 smd: 1(-0.5,0) 2(0.5,0)
R0603
  rect 0.787x0.991 smd: 1(-0.85,0) 2(0.85,0)
R0805
  rect 1.041x1.397 smd: 1(-0.95,0) 2(0.95,0)
R1206
  rect 1.041x1.753 smd: 1(-1.5,0) 2(1.5,0)
R2010H35
  rect 1.499x2.794 smd: 1(-2.311,0) 2(2.311,0)
SO16H104
  rect 0.635x1.88 smd: 1(-4.445,-4.68) 2(-3.175,-4.68) 3(-1.905,-4.68) 4(-0.635,-4.68) 5(0.635,-4.68) 6(1.905,-4.68) 7(3.175,-4.68) 8(4.445,-4.68) 9(4.445,4.68) 10(3.175,4.68) 11(1.905,4.68) 12(0.635,4.68) 13(-0.635,4.68) 14(-1.905,4.68) 15(-3.175,4.68) 16(-4.445,4.68)
SOD123-2
  rect 0.914x1.219 smd: A(1.638,0) C(-1.638,0)
SOD123FL
  rect 0.914x1.219 smd: A(1.638,0) C(-1.638,0)
SOD128
  rect 0.991x1.93 smd: A(2.21,0) C(-2.21,0)
SOD323
  rect 1.27x0.889 smd: A(1.143,0) C(-1.143,0)
SON8
  rect 0.66x1.194 smd: 1(-1.92,-2.828) 2(-0.64,-2.828) 3(0.64,-2.828) 4(1.92,-2.828)
  custom 1.175x1.175 smd: 5(2,3.171)
  round 0.127 smd: 6(0.678,3.211) 7(-0.68,3.236) 8(-2.002,3.223)
TO252
  rect 1.6x2.997 smd: 1(-2.3,-4.063) 3(2.3,-4.063)
  rect 6.706x6.706 smd: 2(0,2.589)
TO252-3
  rect 1.397x2.286 smd: 1(-2.29,-4.191) 2(2.28,-4.191)
  rect 5.69x6.172 smd: 3(0,2.248)
TO263-3
  rect 1.346x4.597 smd: 1(-2.548,-4.574) 3(2.548,-4.574)
  rect 10.795x9.398 smd: 2(0,4.574)
TO-277A
  rect 1.27x1.397 smd: 1(-2.765,-1.065) 2(-2.765,1.065)
  rect 4.724x4.801 smd: 3(1.038,0)
TSSOP28_PAD7_56X3_05
  rect 0.381x1.27 smd: 1(-4.225,-2.81) 2(-3.575,-2.81) 3(-2.925,-2.81) 4(-2.275,-2.81) 5(-1.625,-2.81) 6(-0.975,-2.81) 7(-0.325,-2.81) 8(0.325,-2.81) 9(0.975,-2.81) 10(1.625,-2.81) 11(2.275,-2.81) 12(2.925,-2.81) 13(3.575,-2.81) 14(4.225,-2.81) 15(4.225,2.81) 16(3.575,2.81) 17(2.925,2.81) 18(2.275,2.81) 19(1.625,2.81) 20(0.975,2.81) 21(0.325,2.81) 22(-0.325,2.81) 23(-0.975,2.81) 24(-1.625,2.81) 25(-2.275,2.81) 26(-2.925,2.81) 27(-3.575,2.81) 28(-4.225,2.81)
  rect 7.569x3.048 smd: PAD(0,0)
unnamed#2
  round 4.445 hole 3.175 unplated: (0,0)

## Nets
DGND: C1.2(N2) C4.2(N2) C6.2(N2) C9.2(N2) C14.2(N2) C16.2(N2) C19.2(N2) C22.2(N2) C23.2(N2) C26.2(N2) C29.2(N2) C31.2(N2) C32.2(N2) C33.2(N2) C34.N(N2) CIN1.N(N2) CIN2.2(N2) CIN3.2(N2) CIN4.2(N2) CIN5.2(N2) COUT1.2(N2) COUT2.2(N2) COUT3.2(N2) COUT4.2(N2) COUT5.N(N2) COUT6.N(N2) COUT10.2(N2) COUT11.N(N2) COUT13.2(N2) COUT14.2(N2) COUT15.2(N2) COUT16.N(N2) D2.A(P) D8.A(P) D13.A(P) D14.A(P) DS1.C DS2.C GND.1(N1) GND_3.1(N1) GND_5.1(N1) GNDB.1(N1) GNDB_2.1(N1) GNDB_3.1(N1) GNDB_4.1(N1) J2.1(N1) J4.1(N1) P6.2(N2) Q4.3(S) Q6.3(S) R34.2(N2) R38.2(N2) RS1.2(N2) RS3.2(N2) SNS1.1 TP2.1(N1) U1.20 U2.6 U2.PAD U3.4 U3.9 U4.4 U4.9 VDD1_INPUT.2(N2) VDDB_INPUT.2(N2) VIN_GND.1(N1) VOUT_GND.1(N1)
GND: C3.2(N2) C5.1 C7.1 C8.1 C10.1 C11.1 C13.1 C17.2(N2) C24.2(N2) JP1.3 P1.3(N3) P2.3(N3) P5.2 P8.3(N3) P9.3(N3) R5.2(N2) R7.2(N2) R12.1 R13.1 R14.2(N2) R20.2(N2) R21.2(N2) R24.2(N2) R25.2(N2) R35.2(N2) R37.2(N2) R43.1 R44.1 SNS1.2(N2) U1.24 U1.PAD U2.7
VDD1: C16.1 C23.1 P2.1 P9.1 R3.2(N2) U3.3 U3.8 U4.3 U4.8 VDD1_INPUT.1
VDDA: C18.1 C20.1 C21.1 D7.C R8.1 U3.16 VDDA.1(N1)
VDDA_2: C25.1 C27.1 C28.1 D12.C R27.1 U4.16 VDDA_2.1(N1)
VDDB: C19.1 C22.1 C26.1 C29.1 D4.A(P) D8.C D9.A(P) D13.C SNS2.2(N2) U3.11 U4.11 VDDB.1(N1) VDDB_2.1(N1) VDDB_INPUT.1
VIN: CIN1.P CIN2.1 CIN3.1 CIN4.1 CIN5.1 J3.1(N1) L1.1 L7.1 P1.1 R1.1 R11.1 R47.1 SNS2.1 VIN.1(N1)
_N5: R12.2(N2) U1.5
_N8: C15.2(N2) U2.3
_N15: JP1.2(COM) U2.11(SYNC)
_N19: DS1.A(P) PGOOD_2.1(N1) R2.2(N2) U2.12
_N34: P2.2 R4.1
_N36: C17.1 R5.1 R7.1 U3.6
_N38: D4.C R8.2(N2)
_N44: D6.C R15.2(N2)
_N45: D6.A(P) Q4.1 R18.2(N2)
_N49: D5.C R9.2(N2)
_N50: D5.A(P) Q2.1 R10.2(N2)
_N82: C24.1 R21.1 R24.1 U4.6
_N84: D9.C R27.2(N2)
_N86: D11.C R32.2(N2)
_N87: D11.A(P) Q6.1 R33.2(N2)
_N88: D10.C R28.2(N2)
_N89: D10.A(P) Q5.1 R31.2(N2)
_N98: C7.2(N2) R17.1
_N99: C8.2(N2) R17.2(N2) U1.8
_N102: C10.2(N2) U1.11
_N103: C11.2(N2) R26.1
_N104: C13.2(N2) R26.2(N2) U1.13
_N109: R35.1 U1.16
_N112: R36.1 U1.19
_N114: Q3.1 R36.2(N2)
_N115: Q3.3(S) R23.2(N2) RS3.1
_N118: R37.1 U1.26
_N119: Q1.1 Q1.2 Q1.3(S3) R6.2(N2) RS1.1
_N123: C6.1 U1.22
_N124: R39.1 U1.21
_N125: Q1.4 R39.2(N2)
_N127: D1.1 D1.2 L1.2(N2) L7.2(N2) Q1.5 Q1.6 Q1.7 Q1.8 SW1.1(N1)
_N134: COUT16.P L2.1 L5.1 RS4.2(N2)
_N135: D3.1(NC) D3.2 L2.2(N2) L5.2(N2) Q3.2 SW2.1(N1)
_N143: P8.1 R11.2(N2)
_N147: R41.2(N2) R43.2(N2) U1.1
_N148: CLKOUT.1(N1) U1.2
_N149: EXTCLK.1(N1) U1.3
_N152: R42.2(N2) R44.2(N2) U1.4
_N154: C5.2(N2) U1.6
_N155: R14.1 R16.2(N2) U1.7
_N156: R20.1 R22.2(N2) U1.12
_N159: P9.2 R45.1
_N170: R22.1 R48.2(N2)
_N172: R16.1 R49.2(N2)
_N198: C4.1 R47.2(N2) U2.4
_N214: D14.C DS2.A(P) R50.1
_N230: C30.2(N2) L6.2(N2)
_N232: C30.1 L4.2(N2)
BIAS: C14.1 JP1.1 R2.1 U2.1 U2.8 U2.10
DISABLE: R4.2(N2) U3.5
DISABLE_2: R45.2(N2) U4.5
DRAINB_1: C18.2(N2) C20.2(N2) C21.2(N2) D7.A(P) DRAINB_1.1(N1) GNDA.1(N1) HB.1 L4.1 Q2.3(S) Q4.2 U3.14
DRAINB_2: C25.2(N2) C27.2(N2) C28.2(N2) D12.A(P) DRAINB_2.1(N1) GNDA_2.1(N1) HB.2(N2) L6.1 Q5.3(S) Q6.2 U4.14
EN: P1.2 U2.2
HV_RAIL: DRAINA_1.1(N1) P6.1 Q2.2 Q5.2 R46.2(N2) R50.2(N2) TP3.1(N1)
INTVCC: C3.1 R29.2(N2) R30.1 R41.1 R42.1 U1.25
LX: C15.1 L3.1 U2.5
NOT_PWM: NOT_PWM.1(N1) P5.3(N3) U4.1
OUT: C9.1 L3.2(N2) R3.1 U2.9 UNK5V_RAIL.1
PGOOD1: R29.1 R40.2(N2) U1.18
PGOOD2: PGOOD.1(N1) R30.2(N2) U1.17
PWM: P5.1 PWM.1(N1) U3.1
RUN1: D2.C P8.2 R13.2(N2) RUN.1(N1) U1.9
RUN2: R19.1 R25.1 R40.1 U1.10
S1+: C2.1 R6.1 U1.28
S1-: C2.2(N2) R38.1 U1.27
S2+: C12.1 R23.1 U1.14
S2-: C12.2(N2) R34.1 U1.15
VBIAS: C1.1 R1.2(N2) U1.23(VIN)
VOA_1: R9.1 R10.1 U3.15 VOA_1.1(N1)
VOA_2: R28.1 R31.1 U4.15 VOA_2.1(N1)
VOB_1: R15.1 R18.1 U3.10(VOB) VOB_1.1(N1)
VOB_2: R32.1 R33.1 U4.10(VOB) VOB_2.1(N1)
VOUT1: COUT1.1 COUT2.1 COUT3.1 COUT4.1 COUT5.P COUT6.P COUT13.1 COUT14.1 COUT15.1 D1.3(C) R19.2(N2) R49.1 RS4.1 VOUT1.1(N1)
VOUT_240V: C31.1 C32.1 C33.1 C34.P COUT10.1 COUT11.P D3.3 J1.1(N1) R46.1 R48.1 VOUT_240V.1(N1)

Pads without a net: U3 2 7 12 13; U4 2 7 12 13

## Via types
v1: diameter 0.508, hole 0.254, TOP to BOTTOM, 638 vias
v2: diameter 1.016, hole 0.508, TOP to BOTTOM, 10 vias

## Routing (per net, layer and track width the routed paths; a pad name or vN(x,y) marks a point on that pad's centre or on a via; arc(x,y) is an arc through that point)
DGND: length 47.3
  TOP w0.305: v1(19.13,22.38) 19.18,22.42 C23.2 ; GNDB_3.1 42.22,37.97 Q4.3 ; GNDB_4.1 40.33,16.33 37.85,16.33 36.59,17.59 C26.2 34.47,18.04 C29.2 32.38,17.27 U4.9 ; Q6.3 42.22,5.08 GNDB_2.1 ; C16.2 v1(19.18,55.25) ; U3.9 32.38,50.17 C22.2 34.47,50.93 C19.2 36.59,50.48 D8.A 40.33,49.22 GNDB.1 ; v1(24,100.33) 23.64,100.69 U1.20
  TOP w0.508: GNDB_3.1 37.99,37.96 Q4.3 ; 124.22,36.2 124.22,36.2 ; R38.2 v1(28.96,106.36) ; D2.A v1(13.97,83.88) ; R34.2 v1(20,91.57) ; D14.A 127.5,37.86 v1(127.51,37.85) ; C6.2 28.04,100.09 28.83,99.3 v1(29.2,99.3)
  vias: v1(1.65,88.9) v1(2.92,82.55) v1(2.92,72.39) v1(2.92,68.58) v1(2.92,64.77) v1(2.92,60.96) v1(5.46,88.9) v1(5.46,85.09) v1(5.46,81.28) v1(5.46,77.47) v1(9.27,88.9) v1(9.27,81.28) v1(9.27,77.47) v1(9.27,72.39) v1(9.27,68.58) v1(9.27,64.77) v1(9.27,60.96) v1(11.81,120.65) v1(11.81,116.84) v1(11.81,113.03) v1(15.62,116.84) v1(15.62,113.03) v1(19.43,120.65) v1(19.43,116.84) v1(19.43,113.03) v1(19.43,81.28) v1(19.43,77.47) v1(19.43,73.66) v1(19.43,69.85) v1(19.43,66.04) v1(19.43,62.23) v1(19.43,44.45) v1(19.43,40.64) v1(19.43,36.83) v1(19.43,33.02) v1(19.43,29.21) v1(19.43,13.97) v1(19.43,10.16) v1(19.43,6.35) v1(19.43,3.81) v1(19.68,21.84) v1(19.81,54.73) v1(21.97,128.27) v1(21.97,110.49) v1(22.23,87.25) v1(22.99,87.25) v1(23.24,44.45) v1(23.24,40.64) v1(23.24,36.83) v1(23.24,33.02) v1(23.24,29.21) v1(23.24,3.81) v1(23.88,87.25) v1(25.27,108.33) v1(25.78,128.27) v1(25.91,108.84) v1(26.67,108.84) v1(27.05,3.81) v1(27.43,108.84) v1(28.19,108.84) v1(30.16,108.97) v1(30.73,49.02) v1(30.73,16.13) v1(30.92,108.97) v1(30.86,3.81) v1(31.69,108.97) v1(32.45,108.97) v1(32.64,91.06) v1(33.15,50.04) v1(33.15,17.15) v1(33.66,91.06) v1(34.29,108.97) v1(34.29,16.13) v1(34.54,91.06) v1(34.67,3.81) v1(34.8,49.02) v1(35.05,108.97) v1(35.05,16.13) v1(35.81,108.97) v1(35.81,16.13) v1(36.58,108.97) v1(37.08,14.61) v1(37.21,48.13) v1(37.97,48.13) v1(37.97,14.61) v1(38.35,108.97) v1(38.73,48.13) v1(38.73,14.61) v1(39.12,108.97) v1(39.88,108.97) v1(40.64,108.97) v1(41.02,3.43) v1(41.15,36.32) v1(41.78,3.43) v1(42.04,36.32) v1(42.54,3.43) v1(42.93,36.32) v1(43.31,3.43) v1(43.56,83.82) v1(43.56,15.24) v1(44.58,97.92) v1(45.59,97.92) v1(46.48,97.92) v1(46.74,12.7) v1(47.37,83.82) v1(48.26,97.92) v1(49.28,127.38) v1(49.28,126.49) v1(49.28,125.73) v1(49.28,97.92) v1(49.91,69.85) v1(49.91,66.04) v1(50.16,97.92) v1(51.18,123.19) v1(51.18,83.82) v1(51.18,12.7) v1(51.82,97.92) v1(52.83,127.38) v1(52.83,126.62) v1(52.83,125.73) v1(52.83,97.92) v1(53.72,97.92) v1(54.99,123.19) v1(54.99,83.82) v1(54.99,53.34) v1(54.99,48.26) v1(54.99,43.18) v1(54.99,38.1) v1(54.99,33.02) v1(55.5,97.92) v1(56.52,97.92) v1(56.64,119.25) v1(56.64,118.11) v1(56.64,117.09) v1(56.64,115.95) v1(57.4,97.92) v1(58.8,127) v1(58.8,123.19) v1(58.8,119.38) v1(58.8,115.57) v1(58.8,83.82) v1(59.18,97.92) v1(60.07,69.85) v1(60.2,97.92) v1(60.71,28.58) v1(61.09,97.92) v1(61.34,16.51) v1(61.34,12.7) v1(61.34,8.89) v1(61.34,5.08) v1(62.61,97.92) v1(62.61,83.82) v1(63.63,97.92) v1(63.88,128.27) v1(64.52,97.92) v1(65.15,69.85) v1(65.15,16.51) v1(65.15,12.7) v1(65.15,8.89) v1(65.15,5.08) v1(65.33,120.4) v1(66.04,120.4) v1(66.29,97.92) v1(66.42,83.82) v1(66.75,120.4) v1(67.31,97.92) v1(67.46,120.4) v1(67.69,128.27) v1(68.2,97.92) v1(68.96,69.85) v1(68.96,8.89) v1(68.96,5.08) v1(70.23,83.82) v1(70.23,28.58) v1(70.66,117.6) v1(71.37,117.6) v1(71.5,128.27) v1(72.09,117.6) v1(72.8,117.6) v1(72.77,69.85) v1(74.04,125.73) v1(74.04,121.92) v1(74.04,118.11) v1(74.04,114.3) v1(74.04,110.49) v1(74.04,106.68) v1(74.04,102.87) v1(74.04,99.06) v1(74.04,95.25) v1(74.04,91.44) v1(74.04,87.63) v1(74.04,83.82) v1(75.31,128.27) v1(75.31,20.32) v1(76.58,39.37) v1(76.58,35.56) v1(76.58,31.75) v1(77.85,125.73) v1(77.85,121.92) v1(77.85,118.11) v1(77.85,114.3) v1(77.85,110.49) v1(77.85,106.68) v1(77.85,102.87) v1(77.85,99.06) v1(77.85,95.25) v1(77.85,91.44) v1(77.85,87.63) v1(77.85,83.82) v1(79.12,128.27) v1(79.76,15.49) v1(80.39,39.37) v1(80.39,35.56) v1(80.39,31.75) v1(80.77,15.49) v1(81.66,125.73) v1(81.66,121.92) v1(81.66,118.11) v1(81.66,114.3) v1(81.66,110.49) v1(81.66,106.68) v1(81.66,102.87) v1(81.66,99.06) v1(81.66,95.25) v1(81.66,91.44) v1(81.66,87.63) v1(81.66,83.82) v1(81.66,15.49) v1(82.93,128.27) v1(84.2,39.37) v1(84.2,35.56) v1(84.2,31.75) v1(85.47,125.73) v1(85.47,121.92) v1(85.47,118.11) v1(85.47,114.3) v1(85.47,110.49) v1(85.47,106.68) v1(85.47,102.87) v1(85.47,99.06) v1(85.47,95.25) v1(85.47,91.44) v1(85.47,87.63) v1(85.47,83.82) v1(86.74,128.27) v1(87.88,19.43) v1(87.88,18.67) v1(88.01,39.37) v1(88.01,35.56) v1(88.01,31.75) v1(88.14,118.36) v1(88.14,117.48) v1(88.14,116.46) v1(88.14,115.44) v1(88.14,114.55) v1(88.14,113.67) v1(88.14,112.65) v1(88.14,111.63) v1(89.15,118.36) v1(89.15,117.48) v1(89.15,116.46) v1(89.15,115.44) v1(89.15,114.55) v1(89.15,113.67) v1(89.15,112.65) v1(89.15,111.63) v1(89.28,125.73) v1(89.28,121.92) v1(89.28,110.49) v1(89.28,106.68) v1(89.28,102.87) v1(89.28,99.06) v1(89.28,95.25) v1(89.28,91.44) v1(89.28,87.63) v1(89.28,83.82) v1(90.3,13.46) v1(91.31,16.51) v1(91.31,15.75) v1(91.31,14.99) v1(91.82,39.37) v1(91.82,35.56) v1(91.82,31.75) v1(92.33,101.6) v1(92.33,100.58) v1(92.33,99.57) v1(92.33,98.68) v1(92.33,16.51) v1(92.33,15.75) v1(92.33,14.99) v1(92.58,90.55) v1(92.58,89.54) v1(92.58,88.52) v1(92.58,87.63) v1(92.58,78.87) v1(92.58,77.85) v1(92.58,76.84) v1(92.58,75.95) v1(92.71,70.36) v1(92.71,69.34) v1(92.71,68.33) v1(92.71,67.44) v1(93.09,125.73) v1(93.09,121.92) v1(93.09,110.49) v1(93.09,106.68) v1(93.09,95.25) v1(93.09,83.82) v1(94.36,128.27) v1(95.63,39.37) v1(95.63,35.56) v1(95.63,31.75) v1(96.52,13.72) v1(96.52,12.95) v1(97.92,21.97) v1(99.06,21.08) v1(99.06,20.32) v1(104.52,1.27) v1(108.33,1.27) v1(112.14,1.27) v1(115.95,1.27) v1(119.76,1.27) v1(123.57,1.27) v1(124.84,21.59) v1(127.38,7.62) v1(127.38,1.27) v1(128.02,34.29) v1(128.02,31.12) v1(128.02,27.94) v1(128.02,24.77) v1(128.02,21.59) v1(128.02,18.42) v1(128.02,15.24) v1(128.02,12.06) v1(131.19,37.47) v1(131.19,34.29) v1(131.19,31.12) v1(131.19,27.94) v1(131.19,24.77) v1(131.19,21.59) v1(131.19,18.42) v1(131.19,15.24) v1(131.19,12.06) v1(131.19,7.62) v1(131.19,1.27) v2(28.96,96.14)
GND: length 18.6
  TOP w0.203: U2.7 93.22,13.59 v1(93.22,13.59) ; JP1.3 v1(99.06,16.38) ; R21.2 v1(16.76,19.11) ; C24.2 v1(18.13,18.45) ; R24.2 v1(15.75,17.15)
  TOP w0.254: C8.1 v1(8.03,97.41) ; C10.1 9.46,97.6 v1(9.02,97.16)
  TOP w0.305: v1(19.05,101.66) 20.28,102.89 20.44,102.89 20.84,103.29 U1.24 ; R5.2 16.83,52.01 v1(16.76,51.94) ; C17.2 18.8,51.87 18.49,51.56 18.16,51.56
  TOP w0.508: C13.1 13.1,94.45 v1(13.08,94.44) ; R35.2 22.54,92.77 v1(22.1,93.22) ; C3.2 v1(29.08,103) ; R7.2 15.75,49.91 ; C11.1 v1(15.56,90.7) ; R37.2 v1(28.96,104.58)
  BOTTOM w0.203: R25.2 v1(12.95,93.45)
  vias: v1(1.65,130.81) v1(1.65,124.46) v1(1.65,120.65) v1(1.65,116.84) v1(1.65,113.03) v1(1.65,109.22) v1(1.65,105.41) v1(1.65,101.6) v1(1.65,97.79) v1(1.65,93.98) v1(1.65,83.82) v1(1.65,77.47) v1(1.65,73.66) v1(1.65,69.85) v1(1.65,66.04) v1(1.65,62.23) v1(1.65,58.42) v1(1.65,48.26) v1(1.65,44.45) v1(1.65,40.64) v1(1.65,36.83) v1(1.65,33.02) v1(1.65,22.86) v1(1.65,19.05) v1(1.65,15.24) v1(1.65,11.43) v1(1.65,7.62) v1(5.46,120.65) v1(5.46,116.84) v1(5.46,113.03) v1(5.46,109.22) v1(5.46,97.79) v1(5.46,58.42) v1(5.46,54.61) v1(5.46,50.8) v1(6.1,78.74) v1(6.73,107.95) v1(7.11,101.22) v1(7.11,99.57) v1(7.72,94.74) v1(8,130.81) v1(8,19.05) v1(8,15.24) v1(8,11.43) v1(8,7.62) v1(8,1.27) v1(8.38,106.11) v1(9.02,104.84) v1(9.27,124.46) v1(9.27,120.65) v1(9.27,116.84) v1(9.78,84.58) v1(10.54,110.49) v1(11.56,108.33) v1(11.81,130.81) v1(11.81,19.05) v1(11.81,15.24) v1(11.81,11.43) v1(11.81,7.62) v1(11.81,1.27) v1(14.92,108.94) v1(15.62,1.27) v1(16.89,81.28) v1(16.89,77.47) v1(16.89,73.66) v1(16.89,69.85) v1(16.89,66.04) v1(16.89,62.23) v1(16.89,48.26) v1(16.89,44.45) v1(16.89,40.64) v1(16.89,36.83) v1(16.89,33.02) v1(16.89,29.21) v1(16.89,13.97) v1(16.89,10.16) v1(16.89,6.35) v1(17.91,104.65) v1(17.91,102.62) v1(17.91,100.71) v1(17.91,98.81) v1(18.16,130.81) v1(18.8,106.68) v1(19.05,103.63) v1(19.05,99.69) v1(19.43,1.27) v1(20.07,110.49) v1(20.07,104.65) v1(20.07,102.62) v1(20.07,100.71) v1(20.07,98.81) v1(21.97,130.81) v1(23.24,1.27) v1(25.78,130.81) v1(27.05,1.27) v1(29.59,130.81) v1(30.86,1.27) v1(34.67,1.27) v1(38.48,130.81) v1(38.48,1.27) v1(42.29,130.81) v1(42.29,1.27) v1(46.1,130.81) v1(46.1,1.27) v1(48.64,130.81) v1(49.91,1.27) v1(52.45,130.81) v1(53.72,1.27) v1(56.26,130.81) v1(57.53,1.27) v1(60.07,130.81) v1(61.34,1.27) v1(63.88,130.81) v1(65.15,1.27) v1(67.69,130.81) v1(68.96,1.27) v1(71.5,130.81) v1(72.77,1.27) v1(75.31,130.81) v1(76.58,1.27) v1(79.12,130.81) v1(80.39,1.27) v1(82.93,130.81) v1(84.2,1.27) v1(86.74,130.81) v1(88.01,1.27) v1(90.55,130.81) v1(91.82,1.27) v1(94.36,130.81) v1(95.63,1.27) v1(99.44,1.27)
VDD1: length 8.1
  TOP w0.203: v1(19.05,57.15) 19.18,57.02 C16.1 ; v1(76.92,13.86) 76.9,13.86 76.9,13.84 77.09,13.84 77.51,13.42 R3.2 ; U4.8 20.57,17.27 19.94,16.64 v1(19.94,16.6) ; C23.1 18.67,23.62 18.54,23.75 v1(18.52,23.75)
  TOP w0.305: U3.3 C16.1 ; U4.3 C23.1
  vias: v1(18.41,56.64) v1(18.55,24.46) v1(19.43,17.15) v1(19.56,50.04) v1(19.56,49.28) v1(76.33,13.46)
VDDA: length 15.1
  TOP w0.305: U3.16 33.14,59.06 C21.1 35.23,58.29 C18.1 C20.1 39.89,58.74 D7.C 43.64,60 VDDA.1
VDDA_2: length 22.1
  TOP w0.305: VDDA_2.1 43.64,27.1 D12.C 39.89,25.84 C27.1 C25.1 35.23,25.39 C28.1 33.14,26.16 U4.16
  BOTTOM w0.305: VDDA_2.1 44.98,25.76 R27.1
VDDB: length 26.4
  TOP w0.203: v1(34.54,20.83) 34.75,20.62 34.75,20.6 34.92,20.42 C26.1 ; SNS2.2 v1(29.08,13.22)
  TOP w0.305: U4.11 32.38,19.81 C29.1 34.47,19.04 C26.1 36.59,19.49 37.85,20.75 40.33,20.75 VDDB_2.1 ; VDDB.1 40.33,53.65 D8.C 36.59,52.39 C19.1 34.47,51.94 C22.1 32.38,52.71 U3.11
  BOTTOM w0.203: D9.A 44.45,19.03
  vias: v1(29.08,13.97) v1(33.53,53.72) v1(33.53,52.83) v1(33.53,20.83) v1(33.53,19.94) v1(34.54,53.72) v1(35.56,53.72) v1(35.56,20.83) v1(43.94,20.33) v1(44.45,20.83) v1(44.96,20.33)
VIN: length 4.1
  TOP w0.203: v1(13.59,88.14) 13.53,88.2 R11.1 ; R47.1 83.55,18.05 83.36,18.24 83.36,18.39 83.04,18.72 82.96,18.72 v1(82.8,18.87) ; R1.1 24.26,113.28 24.77,113.79 24.77,113.94 ; SNS2.1 v1(29.08,10.15)
  vias: v1(14.35,88.14) v1(23.88,114.05) v1(24.64,114.05) v1(26.03,114.68) v1(26.8,114.68) v1(27.56,114.68) v1(28.32,114.68) v1(29.08,9.44) v1(30.1,114.68) v1(30.86,114.68) v1(31.62,114.68) v1(32.38,114.68) v1(34.16,114.68) v1(34.92,114.68) v1(35.69,114.68) v1(36.45,114.68) v1(38.23,114.68) v1(38.99,114.68) v1(39.75,114.68) v1(40.51,114.68) v1(49.4,120.14) v1(49.4,119.38) v1(49.4,118.62) v1(49.4,117.86) v1(82.8,18.16)
_N5: length 6.4
  TOP w0.305: R12.2 11.87,106.11 14.69,103.29 U1.5
_N8: length 2
  TOP w0.254: U2.3 88.4,15.98 C15.2
_N15: length 4.5
  TOP w0.254: v1(94.36,16.64) 94.2,16.48 U2.11
  TOP w0.305: v1(96.27,16.38) JP1.2
  BOTTOM w0.305: v1(96.27,16.38) 95.89,16 95.12,16 94.49,16.64 v1(94.36,16.64)
_N19: length 7.5
  TOP w0.254: U2.12 93.68,16.98 93.99,17.28 94.86,17.28 95.19,16.95 R2.2
  TOP w0.305: 95.21,19.09 95.5,18.8 95.5,17.21 R2.2 ; 95.21,19.09 PGOOD_2.1 ; 95.21,19.09 DS1.A
_N34: length 15.7
  TOP w0.305: P2.2 11.05,52.07 12.95,53.98 R4.1
_N36: length 5.5
  TOP w0.305: R7.1 17.5,52.67 R5.1 C17.1 21.1,52.64 U3.6
_N38: length 4.8
  BOTTOM w0.305: R8.2 D4.C
_N44: length 2.4
  TOP w0.305: R15.2 37.1,44.32 D6.C
_N45: length 7.1
  TOP w0.305: Q4.1 41.47,41.8 D6.A 37.1,42.55 R18.2
_N49: length 2.4
  TOP w0.305: D5.C 37.1,64.64 R9.2
_N50: length 23.7
  TOP w0.305: R10.2 37.1,62.87 D5.A 56.76,62.12 58.03,60.85 Q2.1
_N82: length 9.6
  TOP w0.305: R21.1 17.5,19.77 R24.1 15.77,19.75 R21.1 ; R21.1 C24.1 ; C24.1 18.86,19.81 U4.6 21.1,19.75 C24.1
_N84: length 4.5
  BOTTOM w0.305: R27.2 D9.C
_N86: length 2.4
  TOP w0.305: D11.C 37.1,11.43 R32.2
_N87: length 7.1
  TOP w0.305: R33.2 37.1,9.65 D11.A 41.47,8.9 Q6.1
_N88: length 2.4
  TOP w0.305: D10.C 37.1,31.75 R28.2
_N89: length 23.7
  TOP w0.305: R31.2 37.1,29.97 D10.A 56.76,29.22 58.03,27.95 Q5.1
_N98: length 1.2
  TOP w0.305: R17.1 C7.2
_N99: length 9
  TOP w0.305: U1.8 12.9,101.34 12.57,101.01 12.57,100.33 11.9,99.66 R17.2 10.95,98.55 9.31,98.55 C8.2
_N102: length 5.1
  TOP w0.305: C10.2 12.38,97.6 14.17,99.39 U1.11
_N103: length 1.2
  TOP w0.305: C11.2 R26.1
_N104: length 5.8
  TOP w0.305: R26.2 13.92,95.34 C13.2 13.84,96.37 15.56,98.09 U1.13
_N109: length 4.8
  TOP w0.305: R35.1 23.28,97.62 22.82,98.09 U1.16
_N112: length 14.4
  TOP w0.305: v1(25.02,99.44) 24.03,99.44 23.43,100.04 U1.19 ; R36.1 28.83,91.06 v1(28.7,91.19)
  BOTTOM w0.305: v1(28.7,91.19) 28.07,91.82 28.07,96.39 v1(25.02,99.44)
_N114: length 2.1
  TOP w0.305: Q3.1 28.83,86.05 R36.2
_N115: length 20.7
  TOP w0.305: R23.2 18.1,83.76 20.98,80.87 RS3.1 23,80.89 Q3.3
_N118: length 4.5
  TOP w0.305: U1.26 26.39,104.59 R37.1
_N123: length 5.2
  TOP w0.305: C6.1 26.29,100.46 24.76,101.98 22.48,101.98 22.47,101.99 U1.22
_N124: length 17.2
  TOP w0.254: v1(35.05,94.94) 35.18,95.06 R39.1
  TOP w0.305: U1.21 24.26,101.34 v1(24.77,100.84)
  BOTTOM w0.305: v1(35.05,94.94) 32.68,97.31 28.3,97.31 v1(24.77,100.84)
_N143: length 8.6
  TOP w0.305: P8.1 4.35,88.2 R11.2
_N147: length 3.1
  TOP w0.305: R43.2 R41.2 16.24,107.65 U1.1
_N148: length 8
  TOP w0.305: U1.2 15.54,105.24 15.11,105.67 v1(15.11,106.81)
  BOTTOM w0.305: v1(15.11,106.81) 12.45,109.47 CLKOUT.1
_N149: length 13.8
  TOP w0.305: U1.3 15.3,104.59 14.35,105.54 v1(14.35,105.92)
  BOTTOM w0.305: EXTCLK.1 9.27,113.67 9.27,109.09 12.45,105.92 v1(14.35,105.92)
_N152: length 6.8
  TOP w0.305: U1.4 16.19,103.89 15.11,103.89 13.65,105.35 R42.2 R44.2
_N154: length 6.2
  TOP w0.305: C5.2 12.13,104.84 14.33,102.64 U1.6
_N155: length 6.9
  TOP w0.305: R14.1 9.68,101.09 R16.2 12.26,101.99 U1.7
_N156: length 8.1
  TOP w0.305: U1.12 15.3,98.74 12.23,95.67 R22.2 11.34,95.76 R20.1
_N159: length 17.2
  TOP w0.305: P9.2 8.51,21.08 R45.1
_N170: length 2
  TOP w0.305: R48.2 11.34,92.58 R22.1
_N172: length 1.9
  TOP w0.305: R49.2 9.69,102.99 R16.1
_N198: length 7.3
  TOP w0.254: U2.4 89.39,15.48 v1(89.28,15.37)
  TOP w0.305: R47.2 86.21,17.05 C4.1 v1(87.63,17.02)
  BOTTOM w0.305: v1(87.63,17.02) v1(89.28,15.37)
_N214: length 13.4
  TOP w0.508: 124.22,38.74 124.22,37.6 DS2.A ; 124.22,38.74 124.22,38.74 124.22,40 ; 124.22,38.74 D14.C 124.22,40 ; 124.22,40 124.09,39.88 118.13,39.88 R50.1
BIAS: length 16.5
  TOP w0.254: C14.1 94.83,14.35 v1(94.36,14.35) 94.24,14.35 93.64,14.95 93.64,14.95 93.61,14.98 U2.8 ; U2.1 89.7,16.98 v1(89.28,17.4)
  TOP w0.305: JP1.1 97.04,15.38 96.56,14.9 C14.1 95.38,16.19 R2.1 94.91,15.98 U2.10
  BOTTOM w0.254: v1(94.36,14.35) 93.6,15.11 93.6,16.07 92.27,17.4 v1(89.28,17.4)
DISABLE: length 2.7
  TOP w0.305: U3.5 R4.2
DISABLE_2: length 2.7
  TOP w0.305: U4.5 R45.2
DRAINB_1: length 35.1
  TOP w0.305: GNDA.1 43.64,55.57 D7.A 39.89,56.83 C20.2 C18.2 35.23,57.28 C21.2 33.14,56.52 U3.14
  TOP w0.508: DRAINB_1.1 48.89,40.27 Q4.2 ; GNDA.1 58.6,56.26 Q2.3
  vias: v1(47.37,41.91) v1(47.37,40.64) v1(47.37,39.37) v1(47.37,38.1) v1(48.64,41.91) v1(48.64,40.64) v1(48.64,39.37) v1(48.64,38.1) v1(49.91,41.91) v1(49.91,40.64) v1(49.91,39.37) v1(49.91,38.1)
DRAINB_2: length 29.4
  TOP w0.305: GNDA_2.1 43.64,22.68 D12.A 39.89,23.94 C27.2 C25.2 35.23,24.39 C28.2 33.14,23.62 U4.14
  TOP w0.508: GNDA_2.1 58.6,23.37 Q5.3
  vias: v1(47.37,8.89) v1(47.37,7.62) v1(47.37,6.35) v1(47.37,5.08) v1(48.64,8.89) v1(48.64,7.62) v1(48.64,6.35) v1(48.64,5.08) v1(49.91,8.89) v1(49.91,7.62) v1(49.91,6.35) v1(49.91,5.08)
EN: length 81.1
  TOP w0.254: U2.2 89.06,16.48 v1(88.65,16.89)
  BOTTOM w0.254: v1(88.65,16.89) 87.76,17.78 86.61,17.78 85.34,16.51 73.15,16.51 67.82,11.18 39.37,11.18 33.27,5.08 17.03,5.08 16.77,4.83 16.64,4.83
  BOTTOM w0.305: P1.2 16.64,4.83
INTVCC: length 29.8
  TOP w0.381: v2(28.88,98.17) R29.2 R30.1 ; R42.1 13.65,109.33 v2(14.14,109.82) ; U1.25 23.32,103.94 v2(23.69,103.57) ; R41.1 v2(17.14,108.33) ; v2(26.44,101.79) C3.1
  BOTTOM w0.508: v2(28.88,98.17) 26.44,100.61 v2(26.44,101.79) 26.38,101.73 24.64,101.73 23.69,102.68 v2(23.69,103.57) 18.92,108.33 v2(17.14,108.33) 15.66,109.82 v2(14.14,109.82)
LX: length 5.8
  TOP w0.254: U2.5 89.78,14.98 89.48,14.68 88.72,14.68 C15.1
  TOP w0.305: C15.1 86.49,15.01 L3.1
NOT_PWM: length 57.3
  TOP w0.305: NOT_PWM.1 U4.1
  BOTTOM w0.305: P5.3 7.36,70.87 7.37,70.87 7.37,31.75 12.95,26.16 NOT_PWM.1
OUT: length 15.7
  TOP w0.254: v1(94.23,15.37) 94.23,15.37 94.12,15.48 U2.9
  TOP w0.508: v2(87.88,11.43) 85.37,11.43 L3.2
  BOTTOM w0.508: v2(87.88,11.43) 94.87,11.43 95.38,11.94 95.38,14.86 94.87,15.37 v1(94.23,15.37)
PGOOD1: length 13.9
  TOP w0.305: R29.1 24.82,98.17 24.51,98.48 v1(24.51,98.55) 24.47,98.51 24.04,98.51 23.17,99.39 U1.18
  BOTTOM w0.305: R40.2 19.28,93.32 v1(24.51,98.55)
PGOOD2: length 7.5
  TOP w0.305: U1.17 23.05,98.74 25.62,96.18 R30.2 26.07,93.96 PGOOD.1
PWM: length 16.6
  TOP w0.305: U3.1 PWM.1 13.76,62.31 P5.1
RUN1: length 33.3
  TOP w0.305: RUN.1 15.75,86.17 D2.C 12.68,86.19 R13.2 4.36,86.19 P8.2 ; v1(13.33,100.58) 13.44,100.69 U1.9
  BOTTOM w0.305: RUN.1 15.88,88.26 12.06,92.07 12.06,99.94 12.71,100.58 v1(13.33,100.58)
RUN2: length 11.8
  TOP w0.305: U1.10 13.81,100.04 v1(13.02,99.25)
  BOTTOM w0.305: v1(13.02,99.25) 13.91,98.36 R25.1 13.93,95.12 R19.1 15.78,95.02 R40.1
S1+: length 14
  TOP w0.305: U1.28 23.08,105.89 24.04,106.84 C2.1 v1(25.15,106.84) ; R6.1 v1(30.61,102.13)
  BOTTOM w0.305: v1(30.61,102.13) 30.61,105.36 30.3,105.66 26.32,105.66 v1(25.15,106.84)
S1-: length 4.8
  TOP w0.305: R38.1 26.1,106.36 25.62,105.88 C2.2 23.55,105.24 U1.27
S2+: length 5.1
  TOP w0.305: U1.14 16.24,96.66 17.27,95.63 C12.1 18.57,94.73 R23.1
S2-: length 5
  TOP w0.305: R34.1 19.53,94.73 C12.2 20.7,95.63 21.86,96.79 U1.15
VBIAS: length 13.6
  TOP w0.305: v2(25.02,103.12) 25.02,102.94 24.71,102.64 U1.23
  TOP w0.508: R1.2 24.38,110.94 C1.1 23.17,109.47 v2(23.1,109.39)
  BOTTOM w0.508: v2(25.02,103.12) 25.02,105.28 22.99,107.31 22.99,109.29 v2(23.1,109.39)
VOA_1: length 11.7
  TOP w0.305: v1(32.51,57.79) U3.15 ; R9.1 R10.1 VOA_1.1
  BOTTOM w0.305: VOA_1.1 31.62,58.67 v1(32.51,57.79)
VOA_2: length 11.7
  TOP w0.305: v1(32.51,24.89) U4.15 ; VOA_2.1 R31.1 R28.1
  BOTTOM w0.305: v1(32.51,24.89) 31.62,25.78 VOA_2.1
VOB_1: length 13.7
  TOP w0.305: VOB_1.1 R15.1 ; R15.1 R18.1 ; R15.1 v1(34.08,45.68) ; U3.10 32,51.44 v1(32.26,51.18)
  BOTTOM w0.305: v1(32.26,51.18) 32.26,48.26 34.08,46.44 v1(34.08,45.68)
VOB_2: length 14.5
  TOP w0.305: VOB_2.1 R32.1 R33.1 ; v1(28.45,18.16) 28.83,18.54 U4.10
  BOTTOM w0.305: VOB_2.1 31.62,13.21 28.45,16.38 v1(28.45,18.16)
VOUT1: length 0.3
  BOTTOM w0.203: R19.2 15.68,92.9
  vias: v1(6.35,105.54) v1(6.35,104.65) v1(16.37,91.87) v1(16.77,92.46) v1(44.58,103.76) v1(45.47,103.76) v1(46.35,103.76) v1(48.26,103.89) v1(49.15,103.89) v1(49.66,107.57) v1(49.66,106.68) v1(49.66,105.79) v1(50.04,103.89) v1(51.82,103.89) v1(52.7,103.89) v1(53.59,103.89) v1(53.97,105.66) v1(54.86,105.66) v1(55.63,103.76) v1(55.75,105.66) v1(56.39,103.76) v1(57.15,103.76) v1(59.18,103.76) v1(59.94,103.76) v1(60.71,103.76) v1(61.72,113.92) v1(61.72,113.16) v1(62.48,113.92) v1(62.48,113.16) v1(62.74,103.76) v1(63.25,113.92) v1(63.25,113.16) v1(63.63,103.76) v1(64.52,103.76) v1(65.53,105.66) v1(66.29,103.76) v1(66.42,105.66) v1(67.18,103.76) v1(67.31,105.66) v1(68.07,103.76)
VOUT_240V: length 138.7
  TOP w0.508: R48.1 v2(6.44,90.93)
  BOTTOM w0.508: COUT11.P 100.78,84.14 98.93,82.3 9.53,82.3 6.44,85.38 v2(6.44,90.93)

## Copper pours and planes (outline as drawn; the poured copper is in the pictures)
DGND on TOP: 94.74,129.03 94.74,129.03 94.74,64.91 94.73,64.9 91.32,64.9 91.31,64.9 91.31,81.15 91.31,81.15 42.93,81.15 42.93,89.03 32.77,89.03 32.77,70.87 32.89,70.74 75.28,70.74 75.28,67.06 56.77,67.06 56.77,18.54 73.79,18.54 73.79,39.88 131.57,39.88 131.57,0.51 102.62,0.51 102.62,17.78 97.54,17.78 97.54,12.45 94.62,12.45 94.62,14.86 92.33,14.86 92.2,14.73 92.2,8.38 54.36,8.38 54.36,3.18 18.54,3.18 18.54,91.82 21.34,91.82 21.34,101.35 29.97,101.35 29.97,105.79 28.07,105.79 28.07,107.06 21.34,107.06 21.34,112.01 10.41,112.01 10.41,129.03 ; 2 cut-outs
DGND on BOTTOM: outline of 359 points within 10.8,0.51 131.57,131.57 ; 1 cut-out
DGND on LAYER2_GND: 108.97,131.57 131.57,131.57 131.57,95.12 114.94,95.12 114.94,65.66 131.57,65.66 131.57,53.85 120.52,53.85 120.52,43.56 131.57,43.56 131.57,0.51 102.62,0.51 102.62,0.64 97.54,0.64 97.54,0.51 0.51,0.51 0.51,131.57 94.74,131.57 106.81,131.57 ; 2 cut-outs
DGND on LAYER3_PWR: 108.97,131.57 131.57,131.57 131.57,95.12 114.94,95.12 114.94,65.66 131.57,65.66 131.57,53.85 120.52,53.85 120.52,43.56 131.57,43.56 131.57,0.51 102.62,0.51 79.38,0.51 79.38,15.37 70.61,15.37 70.61,3.43 59.18,3.43 59.18,20.57 81.28,20.57 81.28,17.14 84.71,17.14 84.71,27.56 59.18,27.56 59.18,29.84 71.37,29.84 71.37,54.48 59.18,54.48 59.18,89.41 29.85,89.41 29.85,110.74 55.88,110.74 55.88,121.67 47.37,121.67 47.37,127.63 60.2,127.63 60.2,108.46 42.04,108.46 42.04,100.96 68.96,100.96 68.96,107.57 65.28,107.57 65.28,131.57 94.74,131.57 106.81,131.57 ; 1 cut-out
DGND on LAYER3_PWR: outline of 176 points within 0.51,11.18 52.58,117.22
GND on TOP: 0.51,131.57 94.74,131.57 94.74,129.54 10.29,129.54 10.29,111.76 21.08,111.76 21.08,107.95 27.56,107.95 27.56,105.66 30.99,105.66 30.99,100.97 24.13,100.97 24.13,92.07 18.29,92.07 18.29,2.67 54.86,2.67 54.86,7.87 92.71,7.87 92.71,14.73 94.36,14.73 94.36,12.19 97.92,12.19 97.92,17.27 102.11,17.27 102.11,0.51 0.51,0.51 ; 3 cut-outs
GND on BOTTOM: 0.51,131.57 94.74,131.57 94.74,129.54 10.29,129.54 10.29,111.76 24.51,111.76 24.51,107.44 26.54,105.41 29.72,105.41 29.72,101.73 29.59,101.85 22.61,101.85 22.86,101.64 22.86,92.07 18.29,92.07 18.29,2.67 46.35,2.67 46.35,7.87 92.71,7.87 92.71,14.1 94.36,14.1 94.36,12.19 97.92,12.19 97.92,17.27 102.11,17.27 102.11,0.51 0.51,0.51 ; 1 cut-out
VDD1 on TOP: 18.92,48.77 21.97,48.77 21.97,50.55 18.92,50.55
VDD1 on TOP: 18.92,15.88 21.97,15.88 21.97,17.65 18.92,17.65
VDD1 on TOP: 78.36,13.08 78.36,14.22 75.95,14.22 75.95,13.08
VDD1 on TOP: 19.43,23.5 19.43,24.77 18.03,24.77 18.03,23.5
VDD1 on TOP: 19.43,56.39 19.43,57.53 18.03,57.53 18.03,56.39
VDD1 on LAYER3_PWR: 22.1,58.04 22.1,15.88 18.67,15.88 18.67,18.67 3.56,18.67 3.56,10.8 15.88,10.8 15.88,2.92 71.12,2.92 71.12,14.86 78.87,14.86 78.87,0.51 0.51,0.51 0.51,58.04
VDDA on BOTTOM: 51.69,58.29 51.69,60.33 43.43,60.33 43.43,58.29
VDDB on TOP: 28.45,12.57 28.45,14.35 29.72,14.35 29.72,12.57
VDDB on TOP: 41.91,18.92 41.91,21.34 32.77,21.34 32.77,18.92
VDDB on TOP: 42.04,51.63 42.04,54.04 32.89,54.04 32.89,51.63
VDDB on BOTTOM: 39.75,21.46 39.75,19.05 43.31,19.05 43.56,18.8 43.56,16.76 45.34,16.76 45.34,21.46
VDDB on BOTTOM: 43.31,49.28 45.09,49.28 45.09,54.23 40.13,54.23 40.13,52.07 40.39,51.82 43.05,51.82 43.31,51.56
VDDB on LAYER3_PWR: 32.38,54.36 45.47,54.36 45.47,11.43 3.94,11.43 3.94,17.91 18.16,17.91 18.16,15.24 32.38,15.24
VIN on TOP: 84.07,17.78 84.07,19.18 82.04,19.18 82.04,17.78
VIN on TOP: 26.74,128.52 43.94,128.52 43.94,120.9 52.45,120.9 52.45,114.05 59.05,114.05 59.05,108.84 44.07,108.84 44.07,111.89 43.56,112.4 23.49,112.4 23.49,120.9 26.74,120.9
VIN on TOP: 28.45,9.02 28.45,10.8 29.72,10.8 29.72,9.02
VIN on TOP: 12.19,88.77 12.19,87.63 14.99,87.63 14.99,88.77
